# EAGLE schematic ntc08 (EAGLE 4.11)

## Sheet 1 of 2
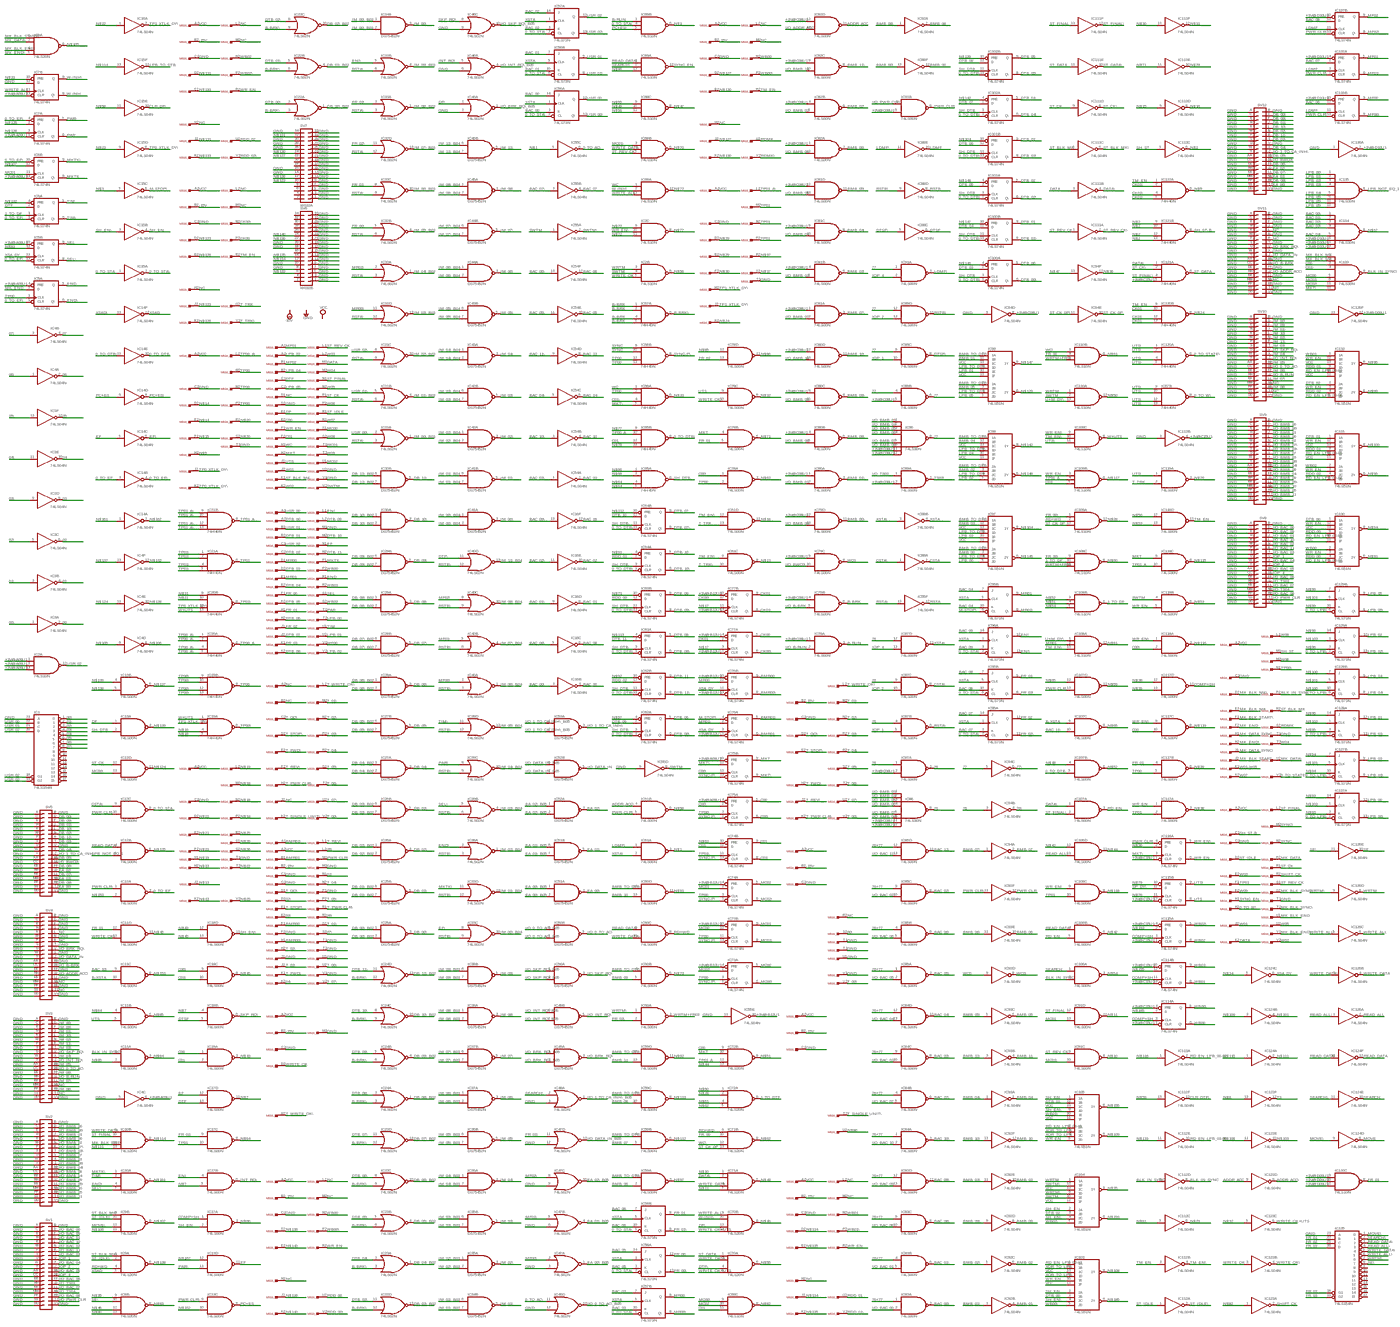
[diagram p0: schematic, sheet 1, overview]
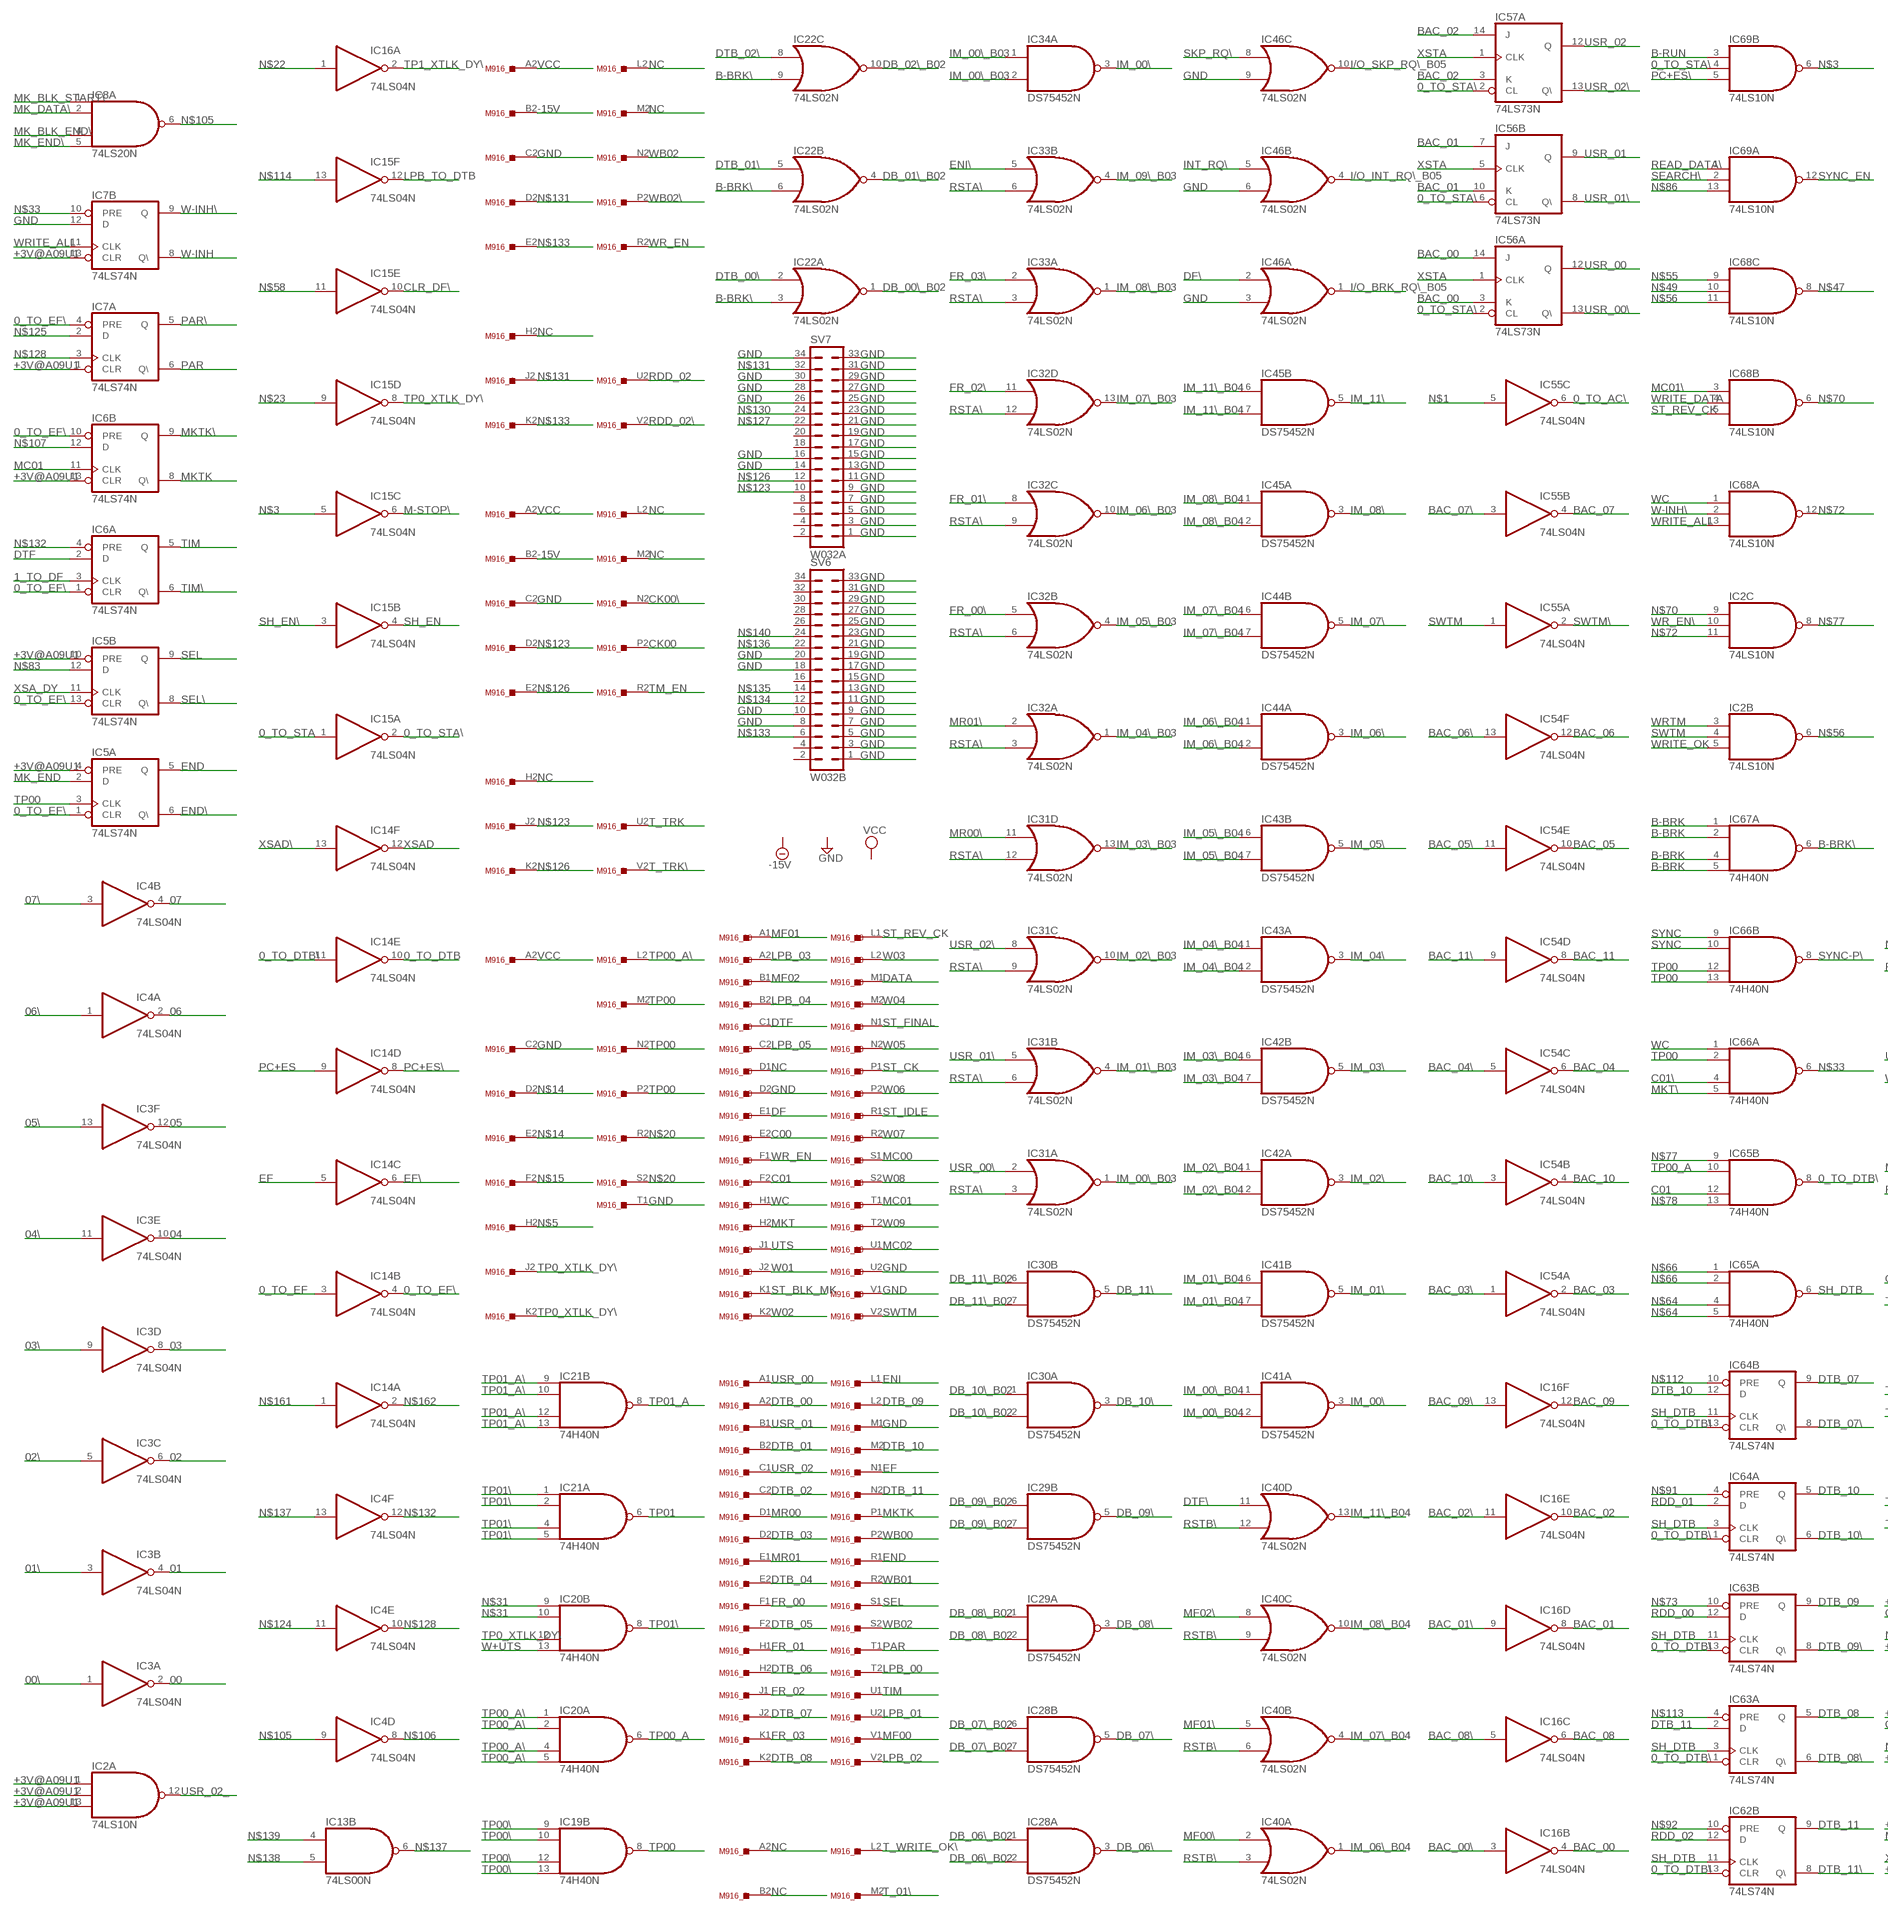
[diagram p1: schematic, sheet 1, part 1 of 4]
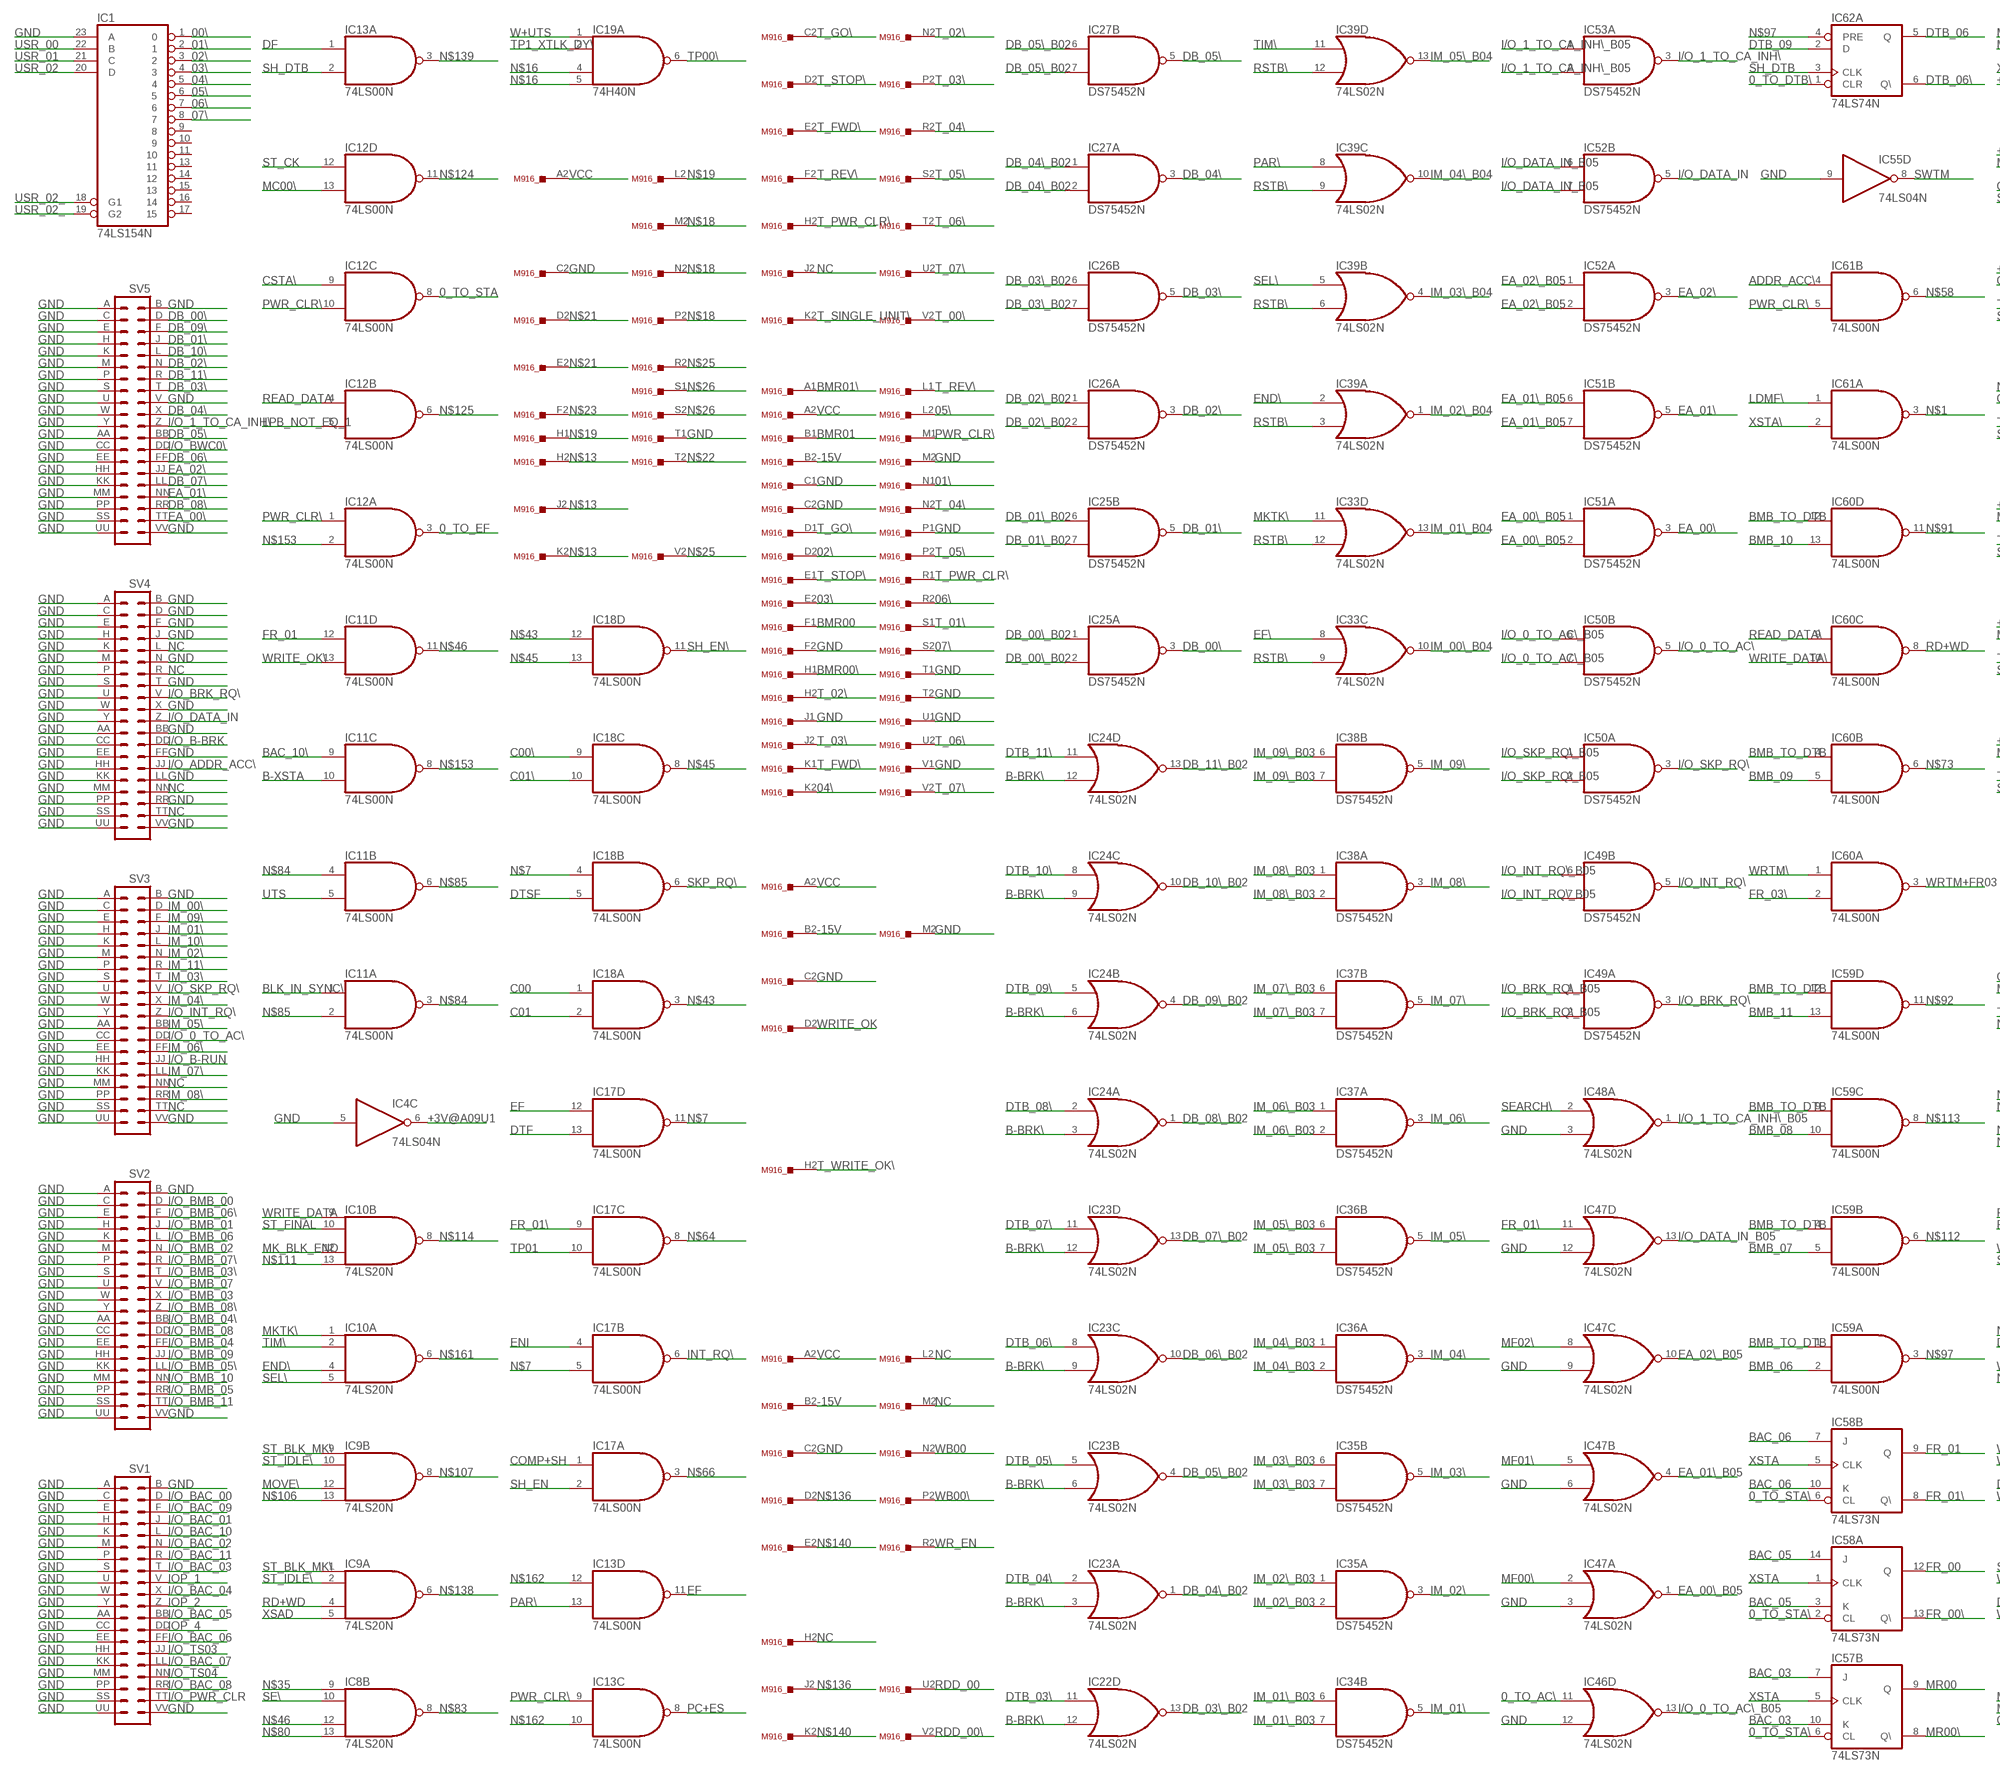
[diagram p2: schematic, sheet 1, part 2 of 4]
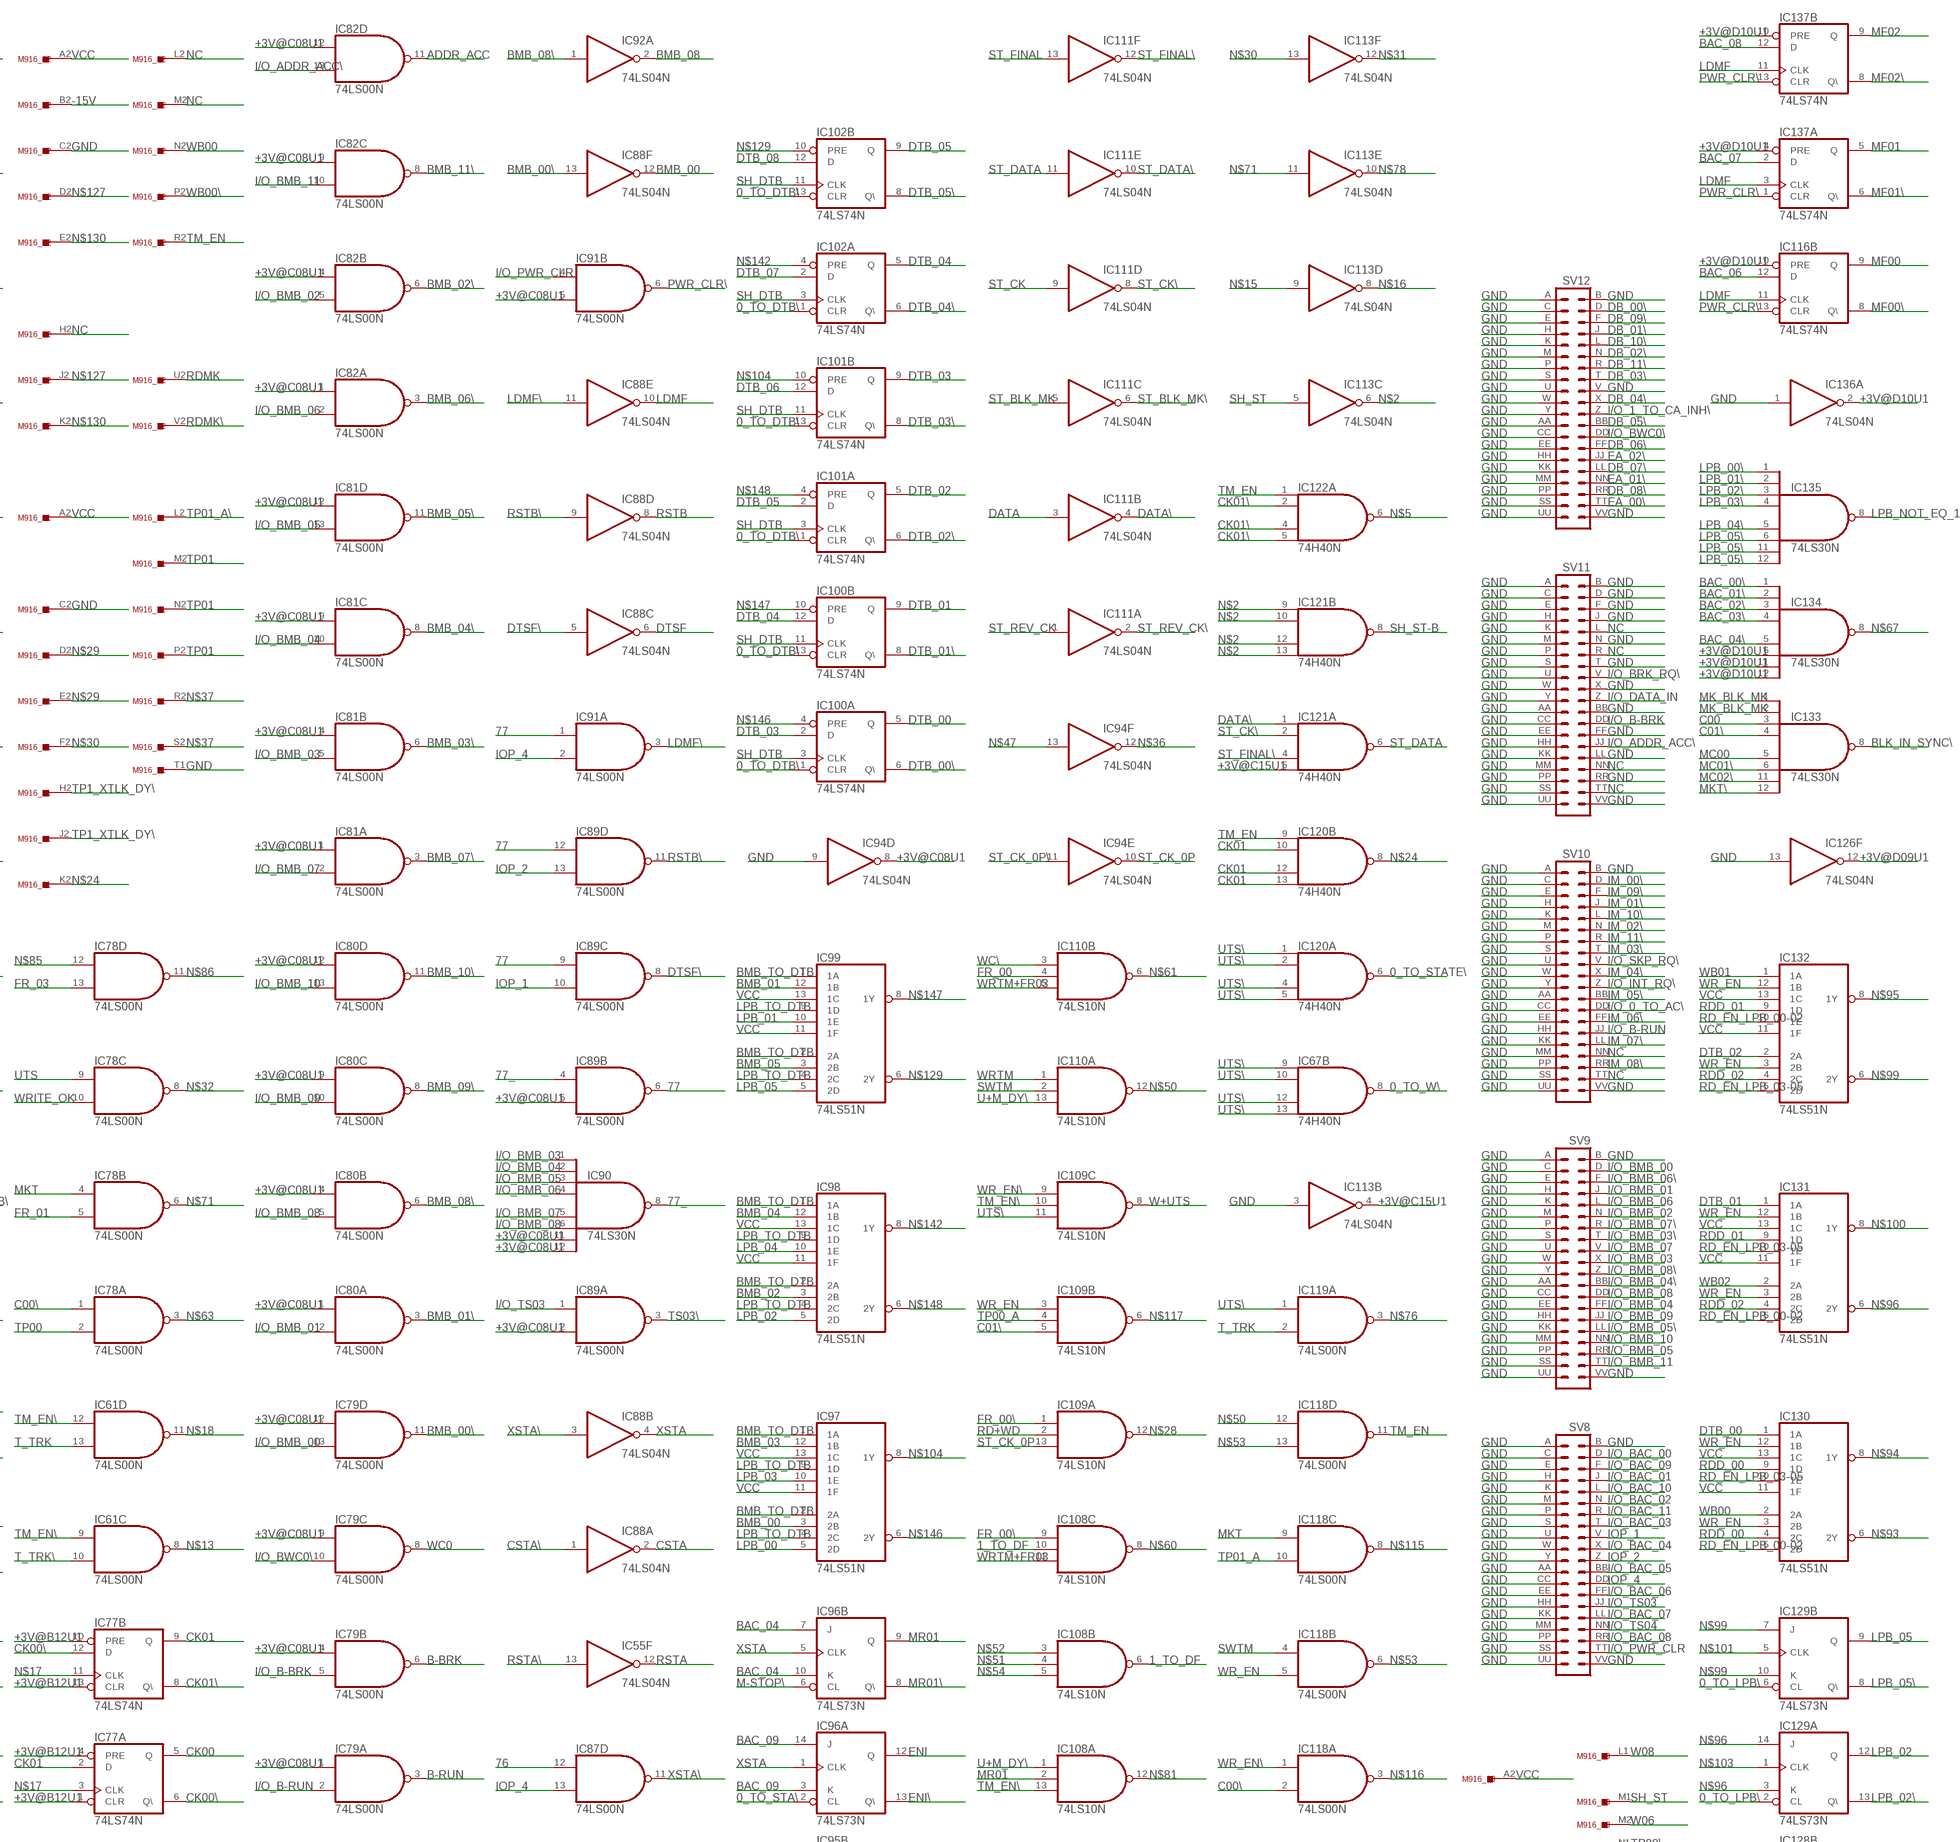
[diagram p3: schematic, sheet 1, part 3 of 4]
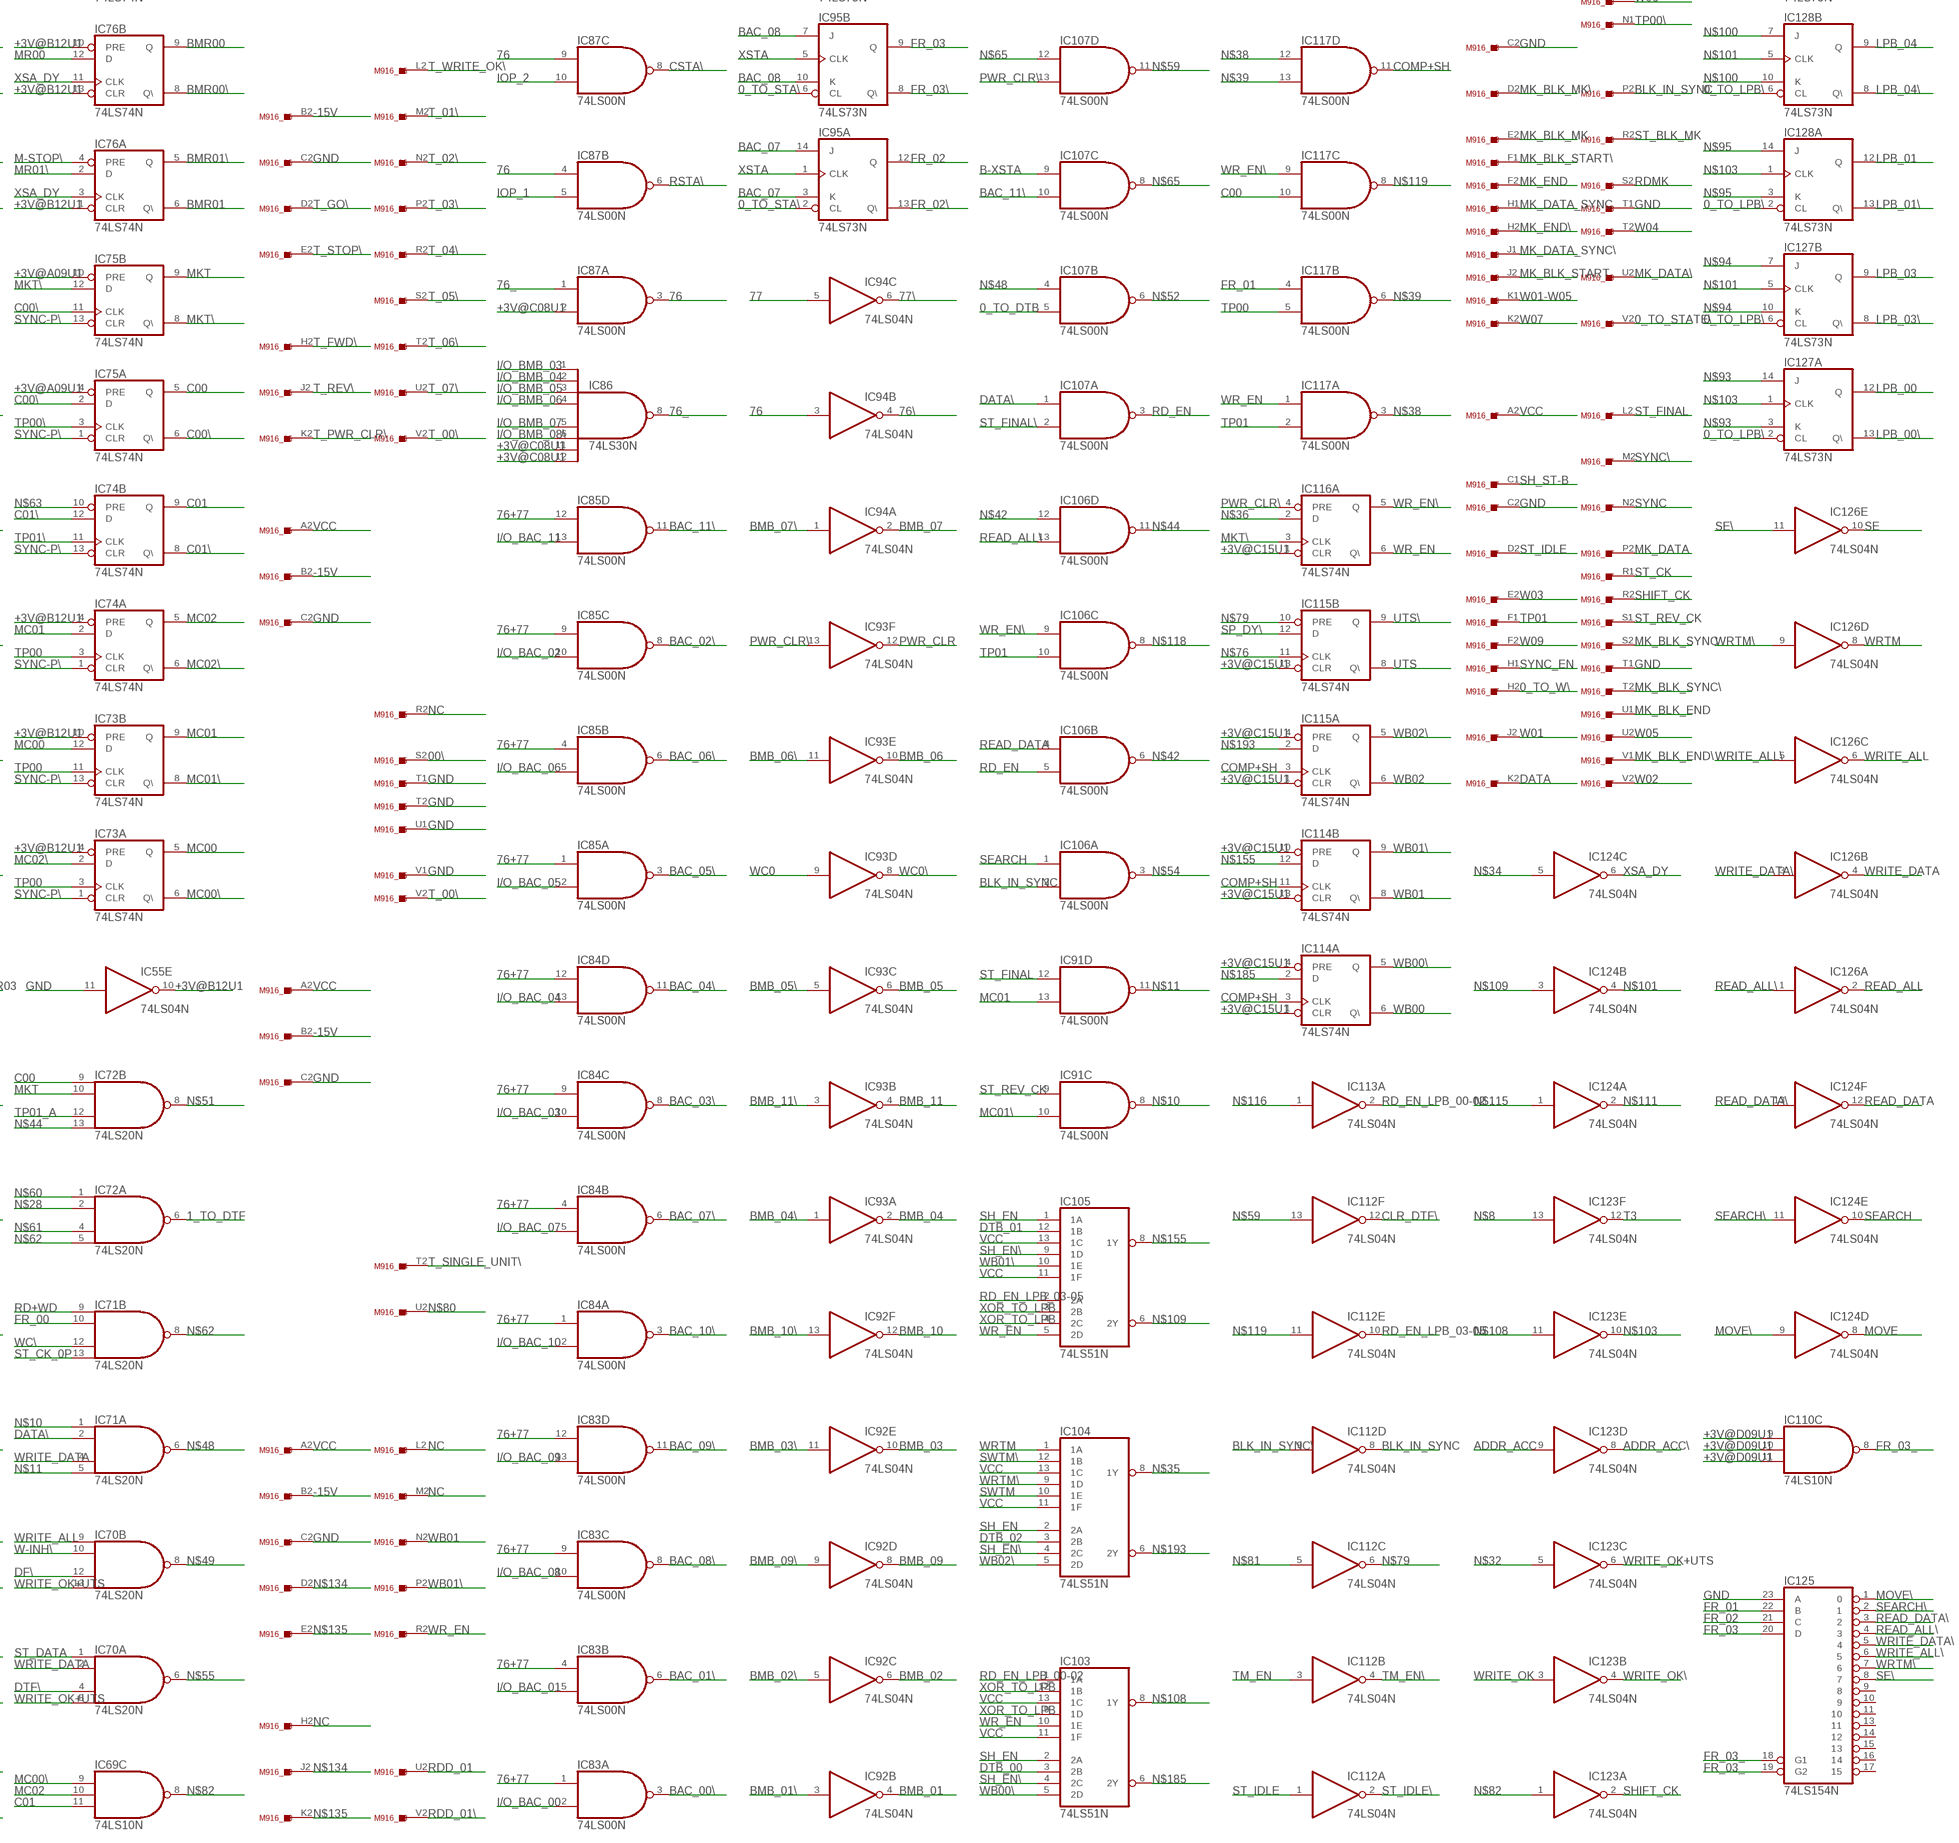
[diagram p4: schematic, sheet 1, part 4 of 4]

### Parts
IC1  74LS154N  [DIL24-6]
IC2  74LS10N  [DIL14]
IC3  74LS04N  [DIL14]
IC4  74LS04N  [DIL14]
IC5  74LS74N  [DIL14]
IC6  74LS74N  [DIL14]
IC7  74LS74N  [DIL14]
IC8  74LS20N  [DIL14]
IC9  74LS20N  [DIL14]
IC10  74LS20N  [DIL14]
IC11  74LS00N  [DIL14]
IC12  74LS00N  [DIL14]
IC13  74LS00N  [DIL14]
IC14  74LS04N  [DIL14]
IC15  74LS04N  [DIL14]
IC16  74LS04N  [DIL14]
IC17  74LS00N  [DIL14]
IC18  74LS00N  [DIL14]
IC19  74H40N  74S20N  [DIL14]
IC20  74H40N  74S20N  [DIL14]
IC21  74H40N  74S20N  [DIL14]
IC22  74LS02N  [DIL14]
IC23  74LS02N  [DIL14]
IC24  74LS02N  [DIL14]
IC25  DS75452N  [DIL08]
IC26  DS75452N  [DIL08]
IC27  DS75452N  [DIL08]
IC28  DS75452N  [DIL08]
IC29  DS75452N  [DIL08]
IC30  DS75452N  [DIL08]
IC31  74LS02N  [DIL14]
IC32  74LS02N  [DIL14]
IC33  74LS02N  [DIL14]
IC34  DS75452N  [DIL08]
IC35  DS75452N  [DIL08]
IC36  DS75452N  [DIL08]
IC37  DS75452N  [DIL08]
IC38  DS75452N  [DIL08]
IC39  74LS02N  [DIL14]
IC40  74LS02N  [DIL14]
IC41  DS75452N  [DIL08]
IC42  DS75452N  [DIL08]
IC43  DS75452N  [DIL08]
IC44  DS75452N  [DIL08]
IC45  DS75452N  [DIL08]
IC46  74LS02N  [DIL14]
IC47  74LS02N  [DIL14]
IC48  74LS02N  [DIL14]
IC49  DS75452N  [DIL08]
IC50  DS75452N  [DIL08]
IC51  DS75452N  [DIL08]
IC52  DS75452N  [DIL08]
IC53  DS75452N  [DIL08]
IC54  74LS04N  [DIL14]
IC55  74LS04N  [DIL14]
IC56  74LS73N  [DIL14]
IC57  74LS73N  [DIL14]
IC58  74LS73N  [DIL14]
IC59  74LS00N  [DIL14]
IC60  74LS00N  [DIL14]
IC61  74LS00N  [DIL14]
IC62  74LS74N  [DIL14]
IC63  74LS74N  [DIL14]
IC64  74LS74N  [DIL14]
IC65  74H40N  74S20N  [DIL14]
IC66  74H40N  74S20N  [DIL14]
IC67  74H40N  74S20N  [DIL14]
IC68  74LS10N  [DIL14]
IC69  74LS10N  [DIL14]
IC70  74LS20N  [DIL14]
IC71  74LS20N  [DIL14]
IC72  74LS20N  [DIL14]
IC73  74LS74N  [DIL14]
IC74  74LS74N  [DIL14]
IC75  74LS74N  [DIL14]
IC76  74LS74N  [DIL14]
IC77  74LS74N  [DIL14]
IC78  74LS00N  [DIL14]
IC79  74LS00N  [DIL14]
IC80  74LS00N  [DIL14]
IC81  74LS00N  [DIL14]
IC82  74LS00N  [DIL14]
IC83  74LS00N  [DIL14]
IC84  74LS00N  [DIL14]
IC85  74LS00N  [DIL14]
IC86  74LS30N  [DIL14]
IC87  74LS00N  [DIL14]
IC88  74LS04N  [DIL14]
IC89  74LS00N  [DIL14]
IC90  74LS30N  [DIL14]
IC91  74LS00N  [DIL14]
IC92  74LS04N  [DIL14]
IC93  74LS04N  [DIL14]
IC94  74LS04N  [DIL14]
IC95  74LS73N  [DIL14]
IC96  74LS73N  [DIL14]
IC97  74LS51N  [DIL14]
IC98  74LS51N  [DIL14]
IC99  74LS51N  [DIL14]
IC100  74LS74N  [DIL14]
IC101  74LS74N  [DIL14]
IC102  74LS74N  [DIL14]
IC103  74LS51N  [DIL14]
IC104  74LS51N  [DIL14]
IC105  74LS51N  [DIL14]
IC106  74LS00N  [DIL14]
IC107  74LS00N  [DIL14]
IC108  74LS10N  [DIL14]
IC109  74LS10N  [DIL14]
IC110  74LS10N  [DIL14]
IC111  74LS04N  [DIL14]
IC112  74LS04N  [DIL14]
IC113  74LS04N  [DIL14]
IC114  74LS74N  [DIL14]
IC115  74LS74N  [DIL14]
IC116  74LS74N  [DIL14]
IC117  74LS00N  [DIL14]
IC118  74LS00N  [DIL14]
IC119  74LS00N  [DIL14]
IC120  74H40N  74S20N  [DIL14]
IC121  74H40N  74S20N  [DIL14]
IC122  74H40N  74S20N  [DIL14]
IC123  74LS04N  [DIL14]
IC124  74LS04N  [DIL14]
IC125  74LS154N  [DIL24-6]
IC126  74LS04N  [DIL14]
IC127  74LS73N  [DIL14]
IC128  74LS73N  [DIL14]
IC129  74LS73N  [DIL14]
IC130  74LS51N  [DIL14]
IC131  74LS51N  [DIL14]
IC132  74LS51N  [DIL14]
IC133  74LS30N  [DIL14]
IC134  74LS30N  [DIL14]
IC135  74LS30N  [DIL14]
IC136  74LS04N  [DIL14]
IC137  74LS74N  [DIL14]
M916_1  M302  M916  [H807]
M916_2  M602  M916  [H807]
M916_3  G888  M916  [H807]
M916_4  M302  M916  [H807]
M916_5  G888  M916  [H807]
M916_6  G888  M916  [H807]
M916_7  M633  M916  [H807]
M916_8  W023  M916  [H807]
M916_9  M916  [H807]
M916_10  M916  [H807]
M916_11  M602  M916  [H807]
M916_12  G888  M916  [H807]
M916_13  G888  M916  [H807]
M916_14  G879  M916  [H807]
M916_15  M633  M916  [H807]
M916_16  W005  M916  [H807]
M916_17  M228B  M916  [H807]
M916_18  M228A  M916  [H807]
SV1  DEC40PIN  [DEC40PIN]
SV2  DEC40PIN  [DEC40PIN]
SV3  DEC40PIN  [DEC40PIN]
SV4  DEC40PIN  [DEC40PIN]
SV5  DEC40PIN  [DEC40PIN]
SV6  W032B  MA17-2  [MA17-2]
SV7  W032A  MA17-2  [MA17-2]
SV8  DEC40PIN  [DEC40PIN]
SV9  DEC40PIN  [DEC40PIN]
SV10  DEC40PIN  [DEC40PIN]
SV11  DEC40PIN  [DEC40PIN]
SV12  DEC40PIN  [DEC40PIN]

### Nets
00: IC3.2(A:O)
00\: IC1.1 IC3.1(A:I) M916_15.S2
0_TO_AC\: IC46.11(D:I0) IC55.6(C:O)
0_TO_DTB: IC14.10(E:O) IC107.5(B:I1)
0_TO_DTB\: IC14.11(E:I) IC62.1(A:CLR) IC62.13(B:CLR) IC63.1(A:CLR) IC63.13(B:CLR) IC64.1(A:CLR) IC64.13(B:CLR) IC65.8(B:O) IC100.1(A:CLR) IC100.13(B:CLR) IC101.1(A:CLR) IC101.13(B:CLR) IC102.1(A:CLR) IC102.13(B:CLR)
0_TO_EF: IC12.3(A:O) IC14.3(B:I)
0_TO_EF\: IC5.1(A:CLR) IC5.13(B:CLR) IC6.1(A:CLR) IC6.10(B:PRE) IC7.4(A:PRE) IC14.4(B:O)
0_TO_LPB\: IC127.2(A:CL) IC127.6(B:CL) IC128.2(A:CL) IC128.6(B:CL) IC129.2(A:CL) IC129.6(B:CL) ; also sheet 2
0_TO_STA: IC12.8(C:O) IC15.1(A:I)
0_TO_STA\: IC15.2(A:O) IC56.2(A:CL) IC56.6(B:CL) IC57.2(A:CL) IC57.6(B:CL) IC58.2(A:CL) IC58.6(B:CL) IC69.4(B:I1) IC95.2(A:CL) IC95.6(B:CL) IC96.2(A:CL)
0_TO_STATE\: IC120.6(A:O) M916_18.V2
0_TO_W\: IC67.8(B:O) M916_17.H2
01: IC3.4(B:O)
01\: IC1.2 IC3.3(B:I) M916_7.N1
1_TO_DF: IC6.3(A:CLK) IC108.6(B:O) IC108.10(C:I1) ; also sheet 2
1_TO_DTF: IC72.6(A:O) ; also sheet 2
02: IC3.6(C:O)
02\: IC1.3 IC3.5(C:I) M916_7.D2
03: IC3.8(D:O)
03\: IC1.4 IC3.9(D:I) M916_7.E2
04: IC3.10(E:O)
04\: IC1.5 IC3.11(E:I) M916_7.K2
05: IC3.12(F:O)
05\: IC1.6 IC3.13(F:I) M916_7.L2
06: IC4.2(A:O)
06\: IC1.7 IC4.1(A:I) M916_7.R2
07: IC4.4(B:O)
07\: IC1.8 IC4.3(B:I) M916_7.S2
76: IC87.3(A:O) IC87.4(B:I0) IC87.9(C:I0) IC87.12(D:I0) IC94.3(B:I)
76+77: IC83.1(A:I0) IC83.4(B:I0) IC83.9(C:I0) IC83.12(D:I0) IC84.1(A:I0) IC84.4(B:I0) IC84.9(C:I0) IC84.12(D:I0) IC85.1(A:I0) IC85.4(B:I0) IC85.9(C:I0) IC85.12(D:I0) ; also sheet 2
76\: IC94.4(B:O) ; also sheet 2
76_: IC86.8(O) IC87.1(A:I0)
77: IC89.6(B:O) IC89.9(C:I0) IC89.12(D:I0) IC91.1(A:I0) IC94.5(C:I)
77\: IC94.6(C:O) ; also sheet 2
77_: IC89.4(B:I0) IC90.8(O)
+3V@A09U1: IC2.1(A:I0) IC2.2(A:I1) IC2.13(A:I2) IC4.6(C:O) IC5.4(A:PRE) IC5.10(B:PRE) IC6.13(B:CLR) IC7.1(A:CLR) IC7.13(B:CLR) IC75.4(A:PRE) IC75.10(B:PRE)
+3V@B12U1: IC55.10(E:O) IC73.4(A:PRE) IC73.10(B:PRE) IC74.4(A:PRE) IC76.1(A:CLR) IC76.10(B:PRE) IC76.13(B:CLR) IC77.1(A:CLR) IC77.4(A:PRE) IC77.10(B:PRE) IC77.13(B:CLR)
+3V@C08U1: IC79.1(A:I0) IC79.4(B:I0) IC79.9(C:I0) IC79.12(D:I0) IC80.1(A:I0) IC80.4(B:I0) IC80.9(C:I0) IC80.12(D:I0) IC81.1(A:I0) IC81.4(B:I0) IC81.9(C:I0) IC81.12(D:I0) IC82.1(A:I0) IC82.4(B:I0) IC82.9(C:I0) IC82.12(D:I0) IC86.11(I6) IC86.12(I7) IC87.2(A:I1) IC89.2(A:I1) IC89.5(B:I1) IC90.11(I6) IC90.12(I7) IC91.5(B:I1) IC94.8(D:O)
+3V@C15U1: IC113.4(B:O) IC114.1(A:CLR) IC114.4(A:PRE) IC114.10(B:PRE) IC114.13(B:CLR) IC115.1(A:CLR) IC115.4(A:PRE) IC115.13(B:CLR) IC116.1(A:CLR) IC121.5(A:I3)
+3V@D09U1: IC110.9(C:I0) IC110.10(C:I1) IC110.11(C:I2) IC126.12(F:O)
+3V@D10U1: IC116.10(B:PRE) IC134.6(I5) IC134.11(I6) IC134.12(I7) IC136.2(A:O) IC137.4(A:PRE) IC137.10(B:PRE) ; also sheet 2
-15V: M916_3.B2 M916_4.B2 M916_5.B2 M916_6.B2 M916_7.B2 M916_12.B2 M916_13.B2 M916_14.B2 M916_15.B2 M916_16.B2
ADDR_ACC: IC82.11(D:O) IC123.9(D:I)
ADDR_ACC\: IC61.4(B:I0) IC123.8(D:O)
B-BRK: IC67.1(A:I0) IC67.2(A:I1) IC67.4(A:I2) IC67.5(A:I3) IC79.6(B:O) ; also sheet 2
B-BRK\: IC22.3(A:I1) IC22.6(B:I1) IC22.9(C:I1) IC22.12(D:I1) IC23.3(A:I1) IC23.6(B:I1) IC23.9(C:I1) IC23.12(D:I1) IC24.3(A:I1) IC24.6(B:I1) IC24.9(C:I1) IC24.12(D:I1) IC67.6(A:O)
B-RUN: IC69.3(B:I0) IC79.3(A:O)
B-XSTA: IC11.10(C:I1) IC107.9(C:I0) ; also sheet 2
BAC_00: IC16.4(B:O) IC56.3(A:K) IC56.14(A:J)
BAC_00\: IC16.3(B:I) IC83.3(A:O) IC134.1(I0)
BAC_01: IC16.8(D:O) IC56.7(B:J) IC56.10(B:K)
BAC_01\: IC16.9(D:I) IC83.6(B:O) IC134.2(I1)
BAC_02: IC16.10(E:O) IC57.3(A:K) IC57.14(A:J)
BAC_02\: IC16.11(E:I) IC85.8(C:O) IC134.3(I2)
BAC_03: IC54.2(A:O) IC57.7(B:J) IC57.10(B:K)
BAC_03\: IC54.1(A:I) IC84.8(C:O) IC134.4(I3)
BAC_04: IC54.6(C:O) IC96.7(B:J) IC96.10(B:K)
BAC_04\: IC54.5(C:I) IC84.11(D:O) IC134.5(I4)
BAC_05: IC54.10(E:O) IC58.3(A:K) IC58.14(A:J)
BAC_05\: IC54.11(E:I) IC85.3(A:O)
BAC_06: IC54.12(F:O) IC58.7(B:J) IC58.10(B:K) IC116.12(B:D)
BAC_06\: IC54.13(F:I) IC85.6(B:O)
BAC_07: IC55.4(B:O) IC95.3(A:K) IC95.14(A:J) IC137.2(A:D)
BAC_07\: IC55.3(B:I) IC84.6(B:O)
BAC_08: IC16.6(C:O) IC95.7(B:J) IC95.10(B:K) IC137.12(B:D)
BAC_08\: IC16.5(C:I) IC83.8(C:O)
BAC_09: IC16.12(F:O) IC96.3(A:K) IC96.14(A:J)
BAC_09\: IC16.13(F:I) IC83.11(D:O)
BAC_10: IC54.4(B:O)
BAC_10\: IC11.9(C:I0) IC54.3(B:I) IC84.3(A:O)
BAC_11: IC54.8(D:O)
BAC_11\: IC54.9(D:I) IC85.11(D:O) IC107.10(C:I1)
BLK_IN_SYNC: IC106.2(A:I1) IC112.8(D:O) M916_18.P2
BLK_IN_SYNC\: IC11.1(A:I0) IC112.9(D:I) IC133.8(O)
BMB_00: IC88.12(F:O) IC97.3(2B)
BMB_00\: IC79.11(D:O) IC88.13(F:I)
BMB_01: IC92.4(B:O) IC99.12(1B)
BMB_01\: IC80.3(A:O) IC92.3(B:I)
BMB_02: IC92.6(C:O) IC98.3(2B)
BMB_02\: IC82.6(B:O) IC92.5(C:I)
BMB_03: IC92.10(E:O) IC97.12(1B)
BMB_03\: IC81.6(B:O) IC92.11(E:I)
BMB_04: IC93.2(A:O) IC98.12(1B)
BMB_04\: IC81.8(C:O) IC93.1(A:I)
BMB_05: IC93.6(C:O) IC99.3(2B)
BMB_05\: IC81.11(D:O) IC93.5(C:I)
BMB_06: IC59.2(A:I1) IC93.10(E:O)
BMB_06\: IC82.3(A:O) IC93.11(E:I)
BMB_07: IC59.5(B:I1) IC94.2(A:O)
BMB_07\: IC81.3(A:O) IC94.1(A:I)
BMB_08: IC59.10(C:I1) IC92.2(A:O)
BMB_08\: IC80.6(B:O) IC92.1(A:I)
BMB_09: IC60.5(B:I1) IC92.8(D:O)
BMB_09\: IC80.8(C:O) IC92.9(D:I)
BMB_10: IC60.13(D:I1) IC92.12(F:O)
BMB_10\: IC80.11(D:O) IC92.13(F:I)
BMB_11: IC59.13(D:I1) IC93.4(B:O)
BMB_11\: IC82.8(C:O) IC93.3(B:I)
BMB_TO_DTB: IC59.1(A:I0) IC59.4(B:I0) IC59.9(C:I0) IC59.12(D:I0) IC60.4(B:I0) IC60.12(D:I0) IC97.1(1A) IC97.2(2A) IC98.1(1A) IC98.2(2A) IC99.1(1A) IC99.2(2A) ; also sheet 2
BMR00: IC76.9(B:Q) M916_7.F1
BMR00\: IC76.8(B:Q\) M916_7.H1
BMR01: IC76.6(A:Q\) M916_7.B1
BMR01\: IC76.5(A:Q) M916_7.A1
C00: IC18.1(A:I0) IC72.9(B:I0) IC75.5(A:Q) IC117.10(C:I1) IC133.3(I2) M916_10.E2
C00\: IC18.9(C:I0) IC75.2(A:D) IC75.6(A:Q\) IC75.11(B:CLK) IC78.1(A:I0) IC118.2(A:I1)
C01: IC18.2(A:I1) IC65.12(B:I2) IC69.11(C:I2) IC74.9(B:Q) M916_10.F2
C01\: IC18.10(C:I1) IC66.4(A:I2) IC74.8(B:Q\) IC74.12(B:D) IC109.5(B:I2) IC133.4(I3)
CK00: IC77.5(A:Q) M916_3.P2
CK00\: IC77.6(A:Q\) IC77.12(B:D) M916_3.N2
CK01: IC77.2(A:D) IC77.9(B:Q) IC120.10(B:I1) IC120.12(B:I2) IC120.13(B:I3)
CK01\: IC77.8(B:Q\) IC122.2(A:I1) IC122.4(A:I2) IC122.5(A:I3)
CLR_DF\: IC15.10(E:O) ; also sheet 2
CLR_DTF\: IC112.12(F:O) ; also sheet 2
COMP+SH: IC17.1(A:I0) IC114.3(A:CLK) IC114.11(B:CLK) IC115.3(A:CLK) IC117.11(D:O)
CSTA: IC88.2(A:O) ; also sheet 2
CSTA\: IC12.9(C:I0) IC87.8(C:O) IC88.1(A:I)
DATA: IC111.3(B:I) M916_10.M1 M916_17.K2
DATA\: IC71.2(A:I1) IC107.1(A:I0) IC111.4(B:O) IC121.1(A:I0)
DB_00\: IC25.3(A:O) SV5.D SV12.D
DB_00\_B02: IC22.1(A:O) IC25.1(A:I0) IC25.2(A:I1)
DB_01\: IC25.5(B:O) SV5.J SV12.J
DB_01\_B02: IC22.4(B:O) IC25.6(B:I0) IC25.7(B:I1)
DB_02\: IC26.3(A:O) SV5.N SV12.N
DB_02\_B02: IC22.10(C:O) IC26.1(A:I0) IC26.2(A:I1)
DB_03\: IC26.5(B:O) SV5.T SV12.T
DB_03\_B02: IC22.13(D:O) IC26.6(B:I0) IC26.7(B:I1)
DB_04\: IC27.3(A:O) SV5.X SV12.X
DB_04\_B02: IC23.1(A:O) IC27.1(A:I0) IC27.2(A:I1)
DB_05\: IC27.5(B:O) SV5.BB SV12.BB
DB_05\_B02: IC23.4(B:O) IC27.6(B:I0) IC27.7(B:I1)
DB_06\: IC28.3(A:O) SV5.FF SV12.FF
DB_06\_B02: IC23.10(C:O) IC28.1(A:I0) IC28.2(A:I1)
DB_07\: IC28.5(B:O) SV5.LL SV12.LL
DB_07\_B02: IC23.13(D:O) IC28.6(B:I0) IC28.7(B:I1)
DB_08\: IC29.3(A:O) SV5.RR SV12.RR
DB_08\_B02: IC24.1(A:O) IC29.1(A:I0) IC29.2(A:I1)
DB_09\: IC29.5(B:O) SV5.F SV12.F
DB_09\_B02: IC24.4(B:O) IC29.6(B:I0) IC29.7(B:I1)
DB_10\: IC30.3(A:O) SV5.L SV12.L
DB_10\_B02: IC24.10(C:O) IC30.1(A:I0) IC30.2(A:I1)
DB_11\: IC30.5(B:O) SV5.R SV12.R
DB_11\_B02: IC24.13(D:O) IC30.6(B:I0) IC30.7(B:I1)
DF: IC13.1(A:I0) M916_10.E1 ; also sheet 2
DF\: IC46.2(A:I0) IC70.12(B:I2) ; also sheet 2
DTB_00: IC100.5(A:Q) IC103.3(2B) IC130.1(1A) M916_9.A2
DTB_00\: IC22.2(A:I0) IC100.6(A:Q\)
DTB_01: IC100.9(B:Q) IC105.12(1B) IC131.1(1A) M916_9.B2
DTB_01\: IC22.5(B:I0) IC100.8(B:Q\)
DTB_02: IC101.5(A:Q) IC104.3(2B) IC132.2(2A) M916_9.C2
DTB_02\: IC22.8(C:I0) IC101.6(A:Q\)
DTB_03: IC100.2(A:D) IC101.9(B:Q) M916_9.D2
DTB_03\: IC22.11(D:I0) IC101.8(B:Q\)
DTB_04: IC100.12(B:D) IC102.5(A:Q) M916_9.E2
DTB_04\: IC23.2(A:I0) IC102.6(A:Q\)
DTB_05: IC101.2(A:D) IC102.9(B:Q) M916_9.F2
DTB_05\: IC23.5(B:I0) IC102.8(B:Q\)
DTB_06: IC62.5(A:Q) IC101.12(B:D) M916_9.H2
DTB_06\: IC23.8(C:I0) IC62.6(A:Q\)
DTB_07: IC64.9(B:Q) IC102.2(A:D) M916_9.J2
DTB_07\: IC23.11(D:I0) IC64.8(B:Q\)
DTB_08: IC63.5(A:Q) IC102.12(B:D) M916_9.K2
DTB_08\: IC24.2(A:I0) IC63.6(A:Q\)
DTB_09: IC62.2(A:D) IC63.9(B:Q) M916_9.L2
DTB_09\: IC24.5(B:I0) IC63.8(B:Q\)
DTB_10: IC64.5(A:Q) IC64.12(B:D) M916_9.M2
DTB_10\: IC24.8(C:I0) IC64.6(A:Q\)
DTB_11: IC62.9(B:Q) IC63.2(A:D) M916_9.N2
DTB_11\: IC24.11(D:I0) IC62.8(B:Q\)
DTF: IC6.2(A:D) IC17.13(D:I1) M916_10.C1 ; also sheet 2
DTF\: IC40.11(D:I0) IC70.4(A:I2) ; also sheet 2
DTSF: IC18.5(B:I1) IC88.6(C:O)
DTSF\: IC88.5(C:I) IC89.8(C:O)
EA_00\: IC51.3(A:O) SV5.TT SV12.TT
EA_00\_B05: IC47.1(A:O) IC51.1(A:I0) IC51.2(A:I1)
EA_01\: IC51.5(B:O) SV5.NN SV12.NN
EA_01\_B05: IC47.4(B:O) IC51.6(B:I0) IC51.7(B:I1)
EA_02\: IC52.3(A:O) SV5.JJ SV12.JJ
EA_02\_B05: IC47.10(C:O) IC52.1(A:I0) IC52.2(A:I1)
EF: IC13.11(D:O) IC14.5(C:I) IC17.12(D:I0) M916_9.N1
EF\: IC14.6(C:O) IC33.8(C:I0)
END: IC5.5(A:Q) M916_9.R1
END\: IC5.6(A:Q\) IC10.4(A:I2) IC39.2(A:I0)
ENI: IC17.4(B:I0) IC96.12(A:Q) M916_9.L1
ENI\: IC33.5(B:I0) IC96.13(A:Q\)
FR_00: IC58.12(A:Q) IC71.10(B:I1) IC110.4(B:I1) M916_9.F1
FR_00\: IC32.5(B:I0) IC58.13(A:Q\) IC108.9(C:I0) IC109.1(A:I0)
FR_01: IC11.12(D:I0) IC58.9(B:Q) IC78.5(B:I1) IC117.4(B:I0) IC125.22(B) M916_9.H1 ; also sheet 2
FR_01\: IC17.9(C:I0) IC32.8(C:I0) IC47.11(D:I0) IC58.8(B:Q\)
FR_02: IC95.12(A:Q) IC125.21(C) M916_9.J1
FR_02\: IC32.11(D:I0) IC95.13(A:Q\)
FR_03: IC78.13(D:I1) IC95.9(B:Q) IC125.20(D) M916_9.K1
FR_03\: IC33.2(A:I0) IC60.2(A:I1) IC95.8(B:Q\)
FR_03_: IC110.8(C:O) IC125.18(G1) IC125.19(G2)
GND: IC1.23(A) IC4.5(C:I) IC7.12(B:D) IC46.3(A:I1) IC46.6(B:I1) IC46.9(C:I1) IC46.12(D:I1) IC47.3(A:I1) IC47.6(B:I1) IC47.9(C:I1) IC47.12(D:I1) IC48.3(A:I1) IC55.9(D:I) IC55.11(E:I) IC94.9(D:I) IC113.3(B:I) IC125.23(A) IC126.13(F:I) IC136.1(A:I) M916_1.C2 M916_1.T1 M916_2.C2 M916_2.T1 M916_3.C2 M916_4.C2 M916_5.C2 M916_6.C2 M916_6.M2 M916_7.C1 M916_7.C2 M916_7.F2 M916_7.J1 M916_7.M2 M916_7.P1 M916_7.T1 M916_7.T2 M916_7.U1 M916_7.V1 M916_9.M1 M916_10.D2 M916_10.U2 M916_10.V1 M916_11.C2 M916_11.T1 M916_12.C2 M916_13.C2 M916_14.C2 M916_15.C2 M916_15.T1 M916_15.T2 M916_15.U1 M916_15.V1 M916_16.C2 M916_17.C2 M916_17.T1 M916_18.C2 M916_18.T1 SV1.A SV1.AA SV1.B SV1.C SV1.CC SV1.E SV1.EE SV1.H SV1.HH SV1.K SV1.KK SV1.M SV1.MM SV1.P SV1.PP SV1.S SV1.SS SV1.U SV1.UU SV1.VV SV1.W SV1.Y SV2.A SV2.AA SV2.B SV2.C SV2.CC SV2.E SV2.EE SV2.H SV2.HH SV2.K SV2.KK SV2.M SV2.MM SV2.P SV2.PP SV2.S SV2.SS SV2.U SV2.UU SV2.VV SV2.W SV2.Y SV3.A SV3.AA SV3.B SV3.C SV3.CC SV3.E SV3.EE SV3.H SV3.HH SV3.K SV3.KK SV3.M SV3.MM SV3.P SV3.PP SV3.S SV3.SS SV3.U SV3.UU SV3.VV SV3.W SV3.Y SV4.A SV4.AA SV4.B SV4.BB SV4.C SV4.CC SV4.D SV4.E SV4.EE SV4.F SV4.FF SV4.H SV4.HH SV4.J SV4.K SV4.KK SV4.LL SV4.M SV4.MM SV4.N SV4.P SV4.PP SV4.RR SV4.S SV4.SS SV4.T SV4.U SV4.UU SV4.VV SV4.W SV4.X SV4.Y SV5.A SV5.AA SV5.B SV5.C SV5.CC SV5.E SV5.EE SV5.H SV5.HH SV5.K SV5.KK SV5.M SV5.MM SV5.P SV5.PP SV5.S SV5.SS SV5.U SV5.UU SV5.V SV5.VV SV5.W SV5.Y SV6.1 SV6.3 SV6.5 SV6.7 SV6.8 SV6.9 SV6.10 SV6.11 SV6.13 SV6.15 SV6.17 SV6.18 SV6.19 SV6.20 SV6.21 SV6.23 SV6.25 SV6.27 SV6.29 SV6.31 SV6.33 SV7.1 SV7.3 SV7.5 SV7.7 SV7.9 SV7.11 SV7.13 SV7.14 SV7.15 SV7.16 SV7.17 SV7.19 SV7.21 SV7.23 SV7.25 SV7.26 SV7.27 SV7.28 SV7.29 SV7.30 SV7.31 SV7.33 SV7.34 SV8.A SV8.AA SV8.B SV8.C SV8.CC SV8.E SV8.EE SV8.H SV8.HH SV8.K SV8.KK SV8.M SV8.MM SV8.P SV8.PP SV8.S SV8.SS SV8.U SV8.UU SV8.VV SV8.W SV8.Y SV9.A SV9.AA SV9.B SV9.C SV9.CC SV9.E SV9.EE SV9.H SV9.HH SV9.K SV9.KK SV9.M SV9.MM SV9.P SV9.PP SV9.S SV9.SS SV9.U SV9.UU SV9.VV SV9.W SV9.Y SV10.A SV10.AA SV10.B SV10.C SV10.CC SV10.E SV10.EE SV10.H SV10.HH SV10.K SV10.KK SV10.M SV10.MM SV10.P SV10.PP SV10.S SV10.SS SV10.U SV10.UU SV10.VV SV10.W SV10.Y SV11.A SV11.AA SV11.B SV11.BB SV11.C SV11.CC SV11.D SV11.E SV11.EE SV11.F SV11.FF SV11.H SV11.HH SV11.J SV11.K SV11.KK SV11.LL SV11.M SV11.MM SV11.N SV11.P SV11.PP SV11.RR SV11.S SV11.SS SV11.T SV11.U SV11.UU SV11.VV SV11.W SV11.X SV11.Y SV12.A SV12.AA SV12.B SV12.C SV12.CC SV12.E SV12.EE SV12.H SV12.HH SV12.K SV12.KK SV12.M SV12.MM SV12.P SV12.PP SV12.S SV12.SS SV12.U SV12.UU SV12.V SV12.VV SV12.W SV12.Y ; also sheet 2
I/O_0_TO_AC\: IC50.5(B:O) SV3.DD SV10.DD
I/O_0_TO_AC\_B05: IC46.13(D:O) IC50.6(B:I0) IC50.7(B:I1)
I/O_1_TO_CA_INH\: IC53.3(A:O) SV5.Z SV12.Z
I/O_1_TO_CA_INH\_B05: IC48.1(A:O) IC53.1(A:I0) IC53.2(A:I1)
I/O_ADDR_ACC\: IC82.13(D:I1) SV4.JJ SV11.JJ
I/O_B-BRK: IC79.5(B:I1) SV4.DD SV11.DD
I/O_B-RUN: IC79.2(A:I1) SV3.JJ SV10.JJ
I/O_BAC_00: IC83.2(A:I1) SV1.D SV8.D
I/O_BAC_01: IC83.5(B:I1) SV1.J SV8.J
I/O_BAC_02: IC85.10(C:I1) SV1.N SV8.N
I/O_BAC_03: IC84.10(C:I1) SV1.T SV8.T
I/O_BAC_04: IC84.13(D:I1) SV1.X SV8.X
I/O_BAC_05: IC85.2(A:I1) SV1.BB SV8.BB
I/O_BAC_06: IC85.5(B:I1) SV1.FF SV8.FF
I/O_BAC_07: IC84.5(B:I1) SV1.LL SV8.LL
I/O_BAC_08: IC83.10(C:I1) SV1.RR SV8.RR
I/O_BAC_09: IC83.13(D:I1) SV1.F SV8.F
I/O_BAC_10: IC84.2(A:I1) SV1.L SV8.L
I/O_BAC_11: IC85.13(D:I1) SV1.R SV8.R
I/O_BMB_00: IC79.13(D:I1) SV2.D SV9.D
I/O_BMB_01: IC80.2(A:I1) SV2.J SV9.J
I/O_BMB_02: IC82.5(B:I1) SV2.N SV9.N
I/O_BMB_03: IC81.5(B:I1) IC86.1(I0) IC90.1(I0) SV2.X SV9.X
I/O_BMB_03\: SV2.T SV9.T
I/O_BMB_04: IC81.10(C:I1) IC86.2(I1) IC90.2(I1) SV2.FF SV9.FF
I/O_BMB_04\: SV2.BB SV9.BB
I/O_BMB_05: IC81.13(D:I1) IC86.3(I2) IC90.3(I2) SV2.RR SV9.RR
I/O_BMB_05\: SV2.LL SV9.LL
I/O_BMB_06: IC82.2(A:I1) IC86.4(I3) IC90.4(I3) SV2.L SV9.L
I/O_BMB_06\: SV2.F SV9.F
I/O_BMB_07: IC81.2(A:I1) IC86.5(I4) IC90.5(I4) SV2.V SV9.V
I/O_BMB_07\: SV2.R SV9.R
I/O_BMB_08: IC80.5(B:I1) IC90.6(I5) SV2.DD SV9.DD
I/O_BMB_08\: IC86.6(I5) SV2.Z SV9.Z
I/O_BMB_09: IC80.10(C:I1) SV2.JJ SV9.JJ
I/O_BMB_10: IC80.13(D:I1) SV2.NN SV9.NN
I/O_BMB_11: IC82.10(C:I1) SV2.TT SV9.TT
I/O_BRK_RQ\: IC49.3(A:O) SV4.V SV11.V
I/O_BRK_RQ\_B05: IC46.1(A:O) IC49.1(A:I0) IC49.2(A:I1)
I/O_BWC0\: IC79.10(C:I1) SV5.DD SV12.DD
I/O_DATA_IN: IC52.5(B:O) SV4.Z SV11.Z
I/O_DATA_IN_B05: IC47.13(D:O) IC52.6(B:I0) IC52.7(B:I1)
I/O_INT_RQ\: IC49.5(B:O) SV3.Z SV10.Z
I/O_INT_RQ\_B05: IC46.4(B:O) IC49.6(B:I0) IC49.7(B:I1)
I/O_PWR_CLR: IC91.4(B:I0) SV1.TT SV8.TT
I/O_SKP_RQ\: IC50.3(A:O) SV3.V SV10.V
I/O_SKP_RQ\_B05: IC46.10(C:O) IC50.1(A:I0) IC50.2(A:I1)
I/O_TS03: IC89.1(A:I0) SV1.JJ SV8.JJ
I/O_TS04: SV1.NN SV8.NN
IM_00\: IC34.3(A:O) IC41.3(A:O) SV3.D SV10.D
IM_00\_B03: IC31.1(A:O) IC34.1(A:I0) IC34.2(A:I1)
IM_00\_B04: IC33.10(C:O) IC41.1(A:I0) IC41.2(A:I1)
IM_01\: IC34.5(B:O) IC41.5(B:O) SV3.J SV10.J
IM_01\_B03: IC31.4(B:O) IC34.6(B:I0) IC34.7(B:I1)
IM_01\_B04: IC33.13(D:O) IC41.6(B:I0) IC41.7(B:I1)
IM_02\: IC35.3(A:O) IC42.3(A:O) SV3.N SV10.N
IM_02\_B03: IC31.10(C:O) IC35.1(A:I0) IC35.2(A:I1)
IM_02\_B04: IC39.1(A:O) IC42.1(A:I0) IC42.2(A:I1)
IM_03\: IC35.5(B:O) IC42.5(B:O) SV3.T SV10.T
IM_03\_B03: IC31.13(D:O) IC35.6(B:I0) IC35.7(B:I1)
IM_03\_B04: IC39.4(B:O) IC42.6(B:I0) IC42.7(B:I1)
IM_04\: IC36.3(A:O) IC43.3(A:O) SV3.X SV10.X
IM_04\_B03: IC32.1(A:O) IC36.1(A:I0) IC36.2(A:I1)
IM_04\_B04: IC39.10(C:O) IC43.1(A:I0) IC43.2(A:I1)
IM_05\: IC36.5(B:O) IC43.5(B:O) SV3.BB SV10.BB
IM_05\_B03: IC32.4(B:O) IC36.6(B:I0) IC36.7(B:I1)
IM_05\_B04: IC39.13(D:O) IC43.6(B:I0) IC43.7(B:I1)
IM_06\: IC37.3(A:O) IC44.3(A:O) SV3.FF SV10.FF
IM_06\_B03: IC32.10(C:O) IC37.1(A:I0) IC37.2(A:I1)
IM_06\_B04: IC40.1(A:O) IC44.1(A:I0) IC44.2(A:I1)
IM_07\: IC37.5(B:O) IC44.5(B:O) SV3.LL SV10.LL
IM_07\_B03: IC32.13(D:O) IC37.6(B:I0) IC37.7(B:I1)
IM_07\_B04: IC40.4(B:O) IC44.6(B:I0) IC44.7(B:I1)
IM_08\: IC38.3(A:O) IC45.3(A:O) SV3.RR SV10.RR
IM_08\_B03: IC33.1(A:O) IC38.1(A:I0) IC38.2(A:I1)
IM_08\_B04: IC40.10(C:O) IC45.1(A:I0) IC45.2(A:I1)
IM_09\: IC38.5(B:O) SV3.F SV10.F
IM_09\_B03: IC33.4(B:O) IC38.6(B:I0) IC38.7(B:I1)
IM_10\: SV3.L SV10.L
IM_11\: IC45.5(B:O) SV3.R SV10.R
IM_11\_B04: IC40.13(D:O) IC45.6(B:I0) IC45.7(B:I1)
INT_RQ\: IC17.6(B:O) IC46.5(B:I0)
IOP_1: IC87.5(B:I1) IC89.10(C:I1) SV1.V SV8.V
IOP_2: IC87.10(C:I1) IC89.13(D:I1) SV1.Z SV8.Z
IOP_4: IC87.13(D:I1) IC91.2(A:I1) SV1.DD SV8.DD
LDMF: IC88.10(E:O) IC116.11(B:CLK) IC137.3(A:CLK) IC137.11(B:CLK)
LDMF\: IC61.1(A:I0) IC88.11(E:I) IC91.3(A:O)
LPB_00: IC97.5(2D) IC127.12(A:Q) M916_9.T2
LPB_00\: IC127.13(A:Q\) IC135.1(I0)
LPB_01: IC99.10(1E) IC128.12(A:Q) M916_9.U2
LPB_01\: IC128.13(A:Q\) IC135.2(I1)
LPB_02: IC98.5(2D) IC129.12(A:Q) M916_9.V2
LPB_02\: IC129.13(A:Q\) IC135.3(I2)
LPB_03: IC97.10(1E) IC127.9(B:Q) M916_10.A2
LPB_03\: IC127.8(B:Q\) IC135.4(I3)
LPB_04: IC98.10(1E) IC128.9(B:Q) M916_10.B2
LPB_04\: IC128.8(B:Q\) IC135.5(I4)
LPB_05: IC99.5(2D) IC129.9(B:Q) M916_10.C2
LPB_05\: IC129.8(B:Q\) IC135.6(I5) IC135.11(I6) IC135.12(I7)
LPB_NOT_EQ_1: IC12.5(B:I1) IC135.8(O)
LPB_TO_DTB: IC15.12(F:O) IC97.4(2C) IC97.9(1D) IC98.4(2C) IC98.9(1D) IC99.4(2C) IC99.9(1D)
M-STOP\: IC15.6(C:O) IC76.4(A:PRE) IC96.6(B:CL) ; also sheet 2
MC00: IC73.5(A:Q) IC73.12(B:D) IC133.5(I4) M916_10.S1
MC00\: IC12.13(D:I1) IC69.9(C:I0) IC73.6(A:Q\)
MC01: IC6.11(B:CLK) IC73.9(B:Q) IC74.2(A:D) IC91.13(D:I1) M916_10.T1
MC01\: IC68.3(B:I0) IC73.8(B:Q\) IC91.10(C:I1) IC133.6(I5)
MC02: IC69.10(C:I1) IC74.5(A:Q) M916_10.U1 ; also sheet 2
MC02\: IC73.2(A:D) IC74.6(A:Q\) IC133.11(I6)
MF00: IC116.9(B:Q) M916_9.V1
MF00\: IC40.2(A:I0) IC47.2(A:I0) IC116.8(B:Q\)
MF01: IC137.5(A:Q) M916_10.A1
MF01\: IC40.5(B:I0) IC47.5(B:I0) IC137.6(A:Q\)
MF02: IC137.9(B:Q) M916_10.B1
MF02\: IC40.8(C:I0) IC47.8(C:I0) IC137.8(B:Q\)
MK_BLK_END: IC10.12(B:I2) M916_17.U1
MK_BLK_END\: IC8.4(A:I2) M916_17.V1
MK_BLK_MK: IC133.1(I0) IC133.2(I1) M916_18.E2
MK_BLK_MK\: M916_18.D2
MK_BLK_START: M916_18.J2
MK_BLK_START\: IC8.1(A:I0) M916_18.F1
MK_BLK_SYNC: M916_17.S2
MK_BLK_SYNC\: M916_17.T2
MK_DATA: M916_17.P2
MK_DATA\: IC8.2(A:I1) M916_18.U2
MK_DATA_SYNC: M916_18.H1
MK_DATA_SYNC\: M916_18.J1
MK_END: IC5.2(A:D) M916_18.F2
MK_END\: IC8.5(A:I3) M916_18.H2
MKT: IC72.10(B:I1) IC75.9(B:Q) IC78.4(B:I0) IC118.9(C:I0) M916_10.H2
MKT\: IC66.5(A:I3) IC75.8(B:Q\) IC75.12(B:D) IC116.3(A:CLK) IC133.12(I7)
MKTK: IC6.8(B:Q\) M916_9.P1
MKTK\: IC6.9(B:Q) IC10.1(A:I0) IC33.11(D:I0)
MOVE: IC124.8(D:O)
MOVE\: IC9.12(B:I2) IC124.9(D:I) IC125.1
MR00: IC57.9(B:Q) IC76.12(B:D) M916_9.D1
MR00\: IC31.11(D:I0) IC57.8(B:Q\)
MR01: IC96.9(B:Q) IC108.2(A:I1) M916_9.E1
MR01\: IC32.2(A:I0) IC76.2(A:D) IC96.8(B:Q\)
N$1: IC55.5(C:I) IC61.3(A:O)
N$2: IC113.6(C:O) IC121.9(B:I0) IC121.10(B:I1) IC121.12(B:I2) IC121.13(B:I3)
N$3: IC15.5(C:I) IC69.6(B:O)
N$5: IC122.6(A:O) M916_2.H2
N$7: IC17.5(B:I1) IC17.11(D:O) IC18.4(B:I0)
N$8: IC123.13(F:I) ; also sheet 2
N$10: IC71.1(A:I0) IC91.8(C:O)
N$11: IC71.5(A:I3) IC91.11(D:O)
N$13: IC61.8(C:O) M916_1.H2 M916_1.J2 M916_1.K2
N$14: M916_2.D2 M916_2.E2
N$15: IC113.9(D:I) M916_2.F2
N$16: IC19.4(A:I2) IC19.5(A:I3) IC113.8(D:O)
N$17: IC77.3(A:CLK) IC77.11(B:CLK) ; also sheet 2
N$18: IC61.11(D:O) M916_1.M2 M916_1.N2 M916_1.P2
N$19: M916_1.H1 M916_1.L2
N$20: M916_2.R2 M916_2.S2
N$21: M916_1.D2 M916_1.E2
N$22: IC16.1(A:I) M916_1.T2
N$23: IC15.9(D:I) M916_1.F2
N$24: IC120.8(B:O) M916_11.K2
N$25: M916_1.R2 M916_1.V2
N$26: M916_1.S1 M916_1.S2
N$28: IC72.2(A:I1) IC109.12(A:O)
N$29: M916_11.D2 M916_11.E2
N$30: IC113.13(F:I) M916_11.F2
N$31: IC20.9(B:I0) IC20.10(B:I1) IC113.12(F:O)
N$32: IC78.8(C:O) IC123.5(C:I)
N$33: IC7.10(B:PRE) IC66.6(A:O)
N$34: IC124.5(C:I) ; also sheet 2
N$35: IC8.9(B:I0) IC104.8(1Y)
N$36: IC94.12(F:O) IC116.2(A:D)
N$37: M916_11.R2 M916_11.S2
N$38: IC117.3(A:O) IC117.12(D:I0)
N$39: IC117.6(B:O) IC117.13(D:I1)
N$42: IC106.6(B:O) IC106.12(D:I0)
N$43: IC18.3(A:O) IC18.12(D:I0)
N$44: IC72.13(B:I3) IC106.11(D:O)
N$45: IC18.8(C:O) IC18.13(D:I1)
N$46: IC8.12(B:I2) IC11.11(D:O)
N$47: IC68.8(C:O) IC94.13(F:I)
N$48: IC71.6(A:O) IC107.4(B:I0)
N$49: IC68.10(C:I1) IC70.8(B:O)
N$50: IC110.12(A:O) IC118.12(D:I0)
N$51: IC72.8(B:O) IC108.4(B:I1)
N$52: IC107.6(B:O) IC108.3(B:I0)
N$53: IC118.6(B:O) IC118.13(D:I1)
N$54: IC106.3(A:O) IC108.5(B:I2)
N$55: IC68.9(C:I0) IC70.6(A:O)
N$56: IC2.6(B:O) IC68.11(C:I2)
N$58: IC15.11(E:I) IC61.6(B:O)
N$59: IC107.11(D:O) IC112.13(F:I)
N$60: IC72.1(A:I0) IC108.8(C:O)
N$61: IC72.4(A:I2) IC110.6(B:O)
N$62: IC71.8(B:O) IC72.5(A:I3)
N$63: IC74.10(B:PRE) IC78.3(A:O)
N$64: IC17.8(C:O) IC65.4(A:I2) IC65.5(A:I3)
N$65: IC107.8(C:O) IC107.12(D:I0)
N$66: IC17.3(A:O) IC65.1(A:I0) IC65.2(A:I1)
N$67: IC134.8(O) ; also sheet 2
N$70: IC2.9(C:I0) IC68.6(B:O)
N$71: IC78.6(B:O) IC113.11(E:I)
N$72: IC2.11(C:I2) IC68.12(A:O)
N$73: IC60.6(B:O) IC63.10(B:PRE)
N$76: IC115.11(B:CLK) IC119.3(A:O)
N$77: IC2.8(C:O) IC65.9(B:I0)
N$78: IC65.13(B:I3) IC113.10(E:O)
N$79: IC112.6(C:O) IC115.10(B:PRE)
N$80: IC8.13(B:I3) M916_14.U2
N$81: IC108.12(A:O) IC112.5(C:I)
N$82: IC69.8(C:O) IC123.1(A:I)
N$83: IC5.12(B:D) IC8.8(B:O)
N$84: IC11.3(A:O) IC11.4(B:I0)
N$85: IC11.2(A:I1) IC11.6(B:O) IC78.12(D:I0)
N$86: IC69.13(A:I2) IC78.11(D:O)
N$91: IC60.11(D:O) IC64.4(A:PRE)
N$92: IC59.11(D:O) IC62.10(B:PRE)
N$93: IC127.3(A:K) IC127.14(A:J) IC130.6(2Y)
N$94: IC127.7(B:J) IC127.10(B:K) IC130.8(1Y)
N$95: IC128.3(A:K) IC128.14(A:J) IC132.8(1Y)
N$96: IC129.3(A:K) IC129.14(A:J) IC131.6(2Y)
N$97: IC59.3(A:O) IC62.4(A:PRE)
N$99: IC129.7(B:J) IC129.10(B:K) IC132.6(2Y)
N$100: IC128.7(B:J) IC128.10(B:K) IC131.8(1Y)
N$101: IC124.4(B:O) IC127.5(B:CLK) IC128.5(B:CLK) IC129.5(B:CLK)
N$103: IC123.10(E:O) IC127.1(A:CLK) IC128.1(A:CLK) IC129.1(A:CLK)
N$104: IC97.8(1Y) IC101.10(B:PRE)
N$105: IC4.9(D:I) IC8.6(A:O)
N$106: IC4.8(D:O) IC9.13(B:I3)
N$107: IC6.12(B:D) IC9.8(B:O)
N$108: IC103.8(1Y) IC123.11(E:I)
N$109: IC105.6(2Y) IC124.3(B:I)
N$111: IC10.13(B:I3) IC124.2(A:O)
N$112: IC59.6(B:O) IC64.10(B:PRE)
N$113: IC59.8(C:O) IC63.4(A:PRE)
N$114: IC10.8(B:O) IC15.13(F:I)
N$115: IC118.8(C:O) IC124.1(A:I)
N$116: IC113.1(A:I) IC118.3(A:O)
N$117: IC109.6(B:O) ; also sheet 2
N$118: IC106.8(C:O) ; also sheet 2
N$119: IC112.11(E:I) IC117.8(C:O)
N$123: M916_3.D2 M916_3.J2 SV7.10
N$124: IC4.11(E:I) IC12.11(D:O)
N$125: IC7.2(A:D) IC12.6(B:O)
N$126: M916_3.E2 M916_3.K2 SV7.12
N$127: M916_12.D2 M916_12.J2 SV7.22
N$128: IC4.10(E:O) IC7.3(A:CLK)
N$129: IC99.6(2Y) IC102.10(B:PRE)
N$130: M916_12.E2 M916_12.K2 SV7.24
N$131: M916_4.D2 M916_4.J2 SV7.32
N$132: IC4.12(F:O) IC6.4(A:PRE)
N$133: M916_4.E2 M916_4.K2 SV6.6
N$134: M916_13.D2 M916_13.J2 SV6.12
N$135: M916_13.E2 M916_13.K2 SV6.14
N$136: M916_5.D2 M916_5.J2 SV6.22
N$137: IC4.13(F:I) IC13.6(B:O)
N$138: IC9.6(A:O) IC13.5(B:I1)
N$139: IC13.3(A:O) IC13.4(B:I0)
N$140: M916_5.E2 M916_5.K2 SV6.24
N$142: IC98.8(1Y) IC102.4(A:PRE)
N$146: IC97.6(2Y) IC100.4(A:PRE)
N$147: IC99.8(1Y) IC100.10(B:PRE)
N$148: IC98.6(2Y) IC101.4(A:PRE)
N$153: IC11.8(C:O) IC12.2(A:I1)
N$155: IC105.8(1Y) IC114.12(B:D)
N$161: IC10.6(A:O) IC14.1(A:I)
N$162: IC13.10(C:I1) IC13.12(D:I0) IC14.2(A:O)
N$185: IC103.6(2Y) IC114.2(A:D)
N$193: IC104.6(2Y) IC115.2(A:D)
NC: M916_3.H2 M916_3.L2 M916_3.M2 M916_4.H2 M916_4.L2 M916_4.M2 M916_5.H2 M916_5.L2 M916_5.M2 M916_8.A2 M916_8.B2 M916_8.J2 M916_10.D1 M916_12.H2 M916_12.L2 M916_12.M2 M916_13.H2 M916_13.L2 M916_13.M2 M916_15.R2 SV3.NN SV3.TT SV4.L SV4.NN SV4.R SV4.TT SV10.NN SV10.TT SV11.L SV11.NN SV11.R SV11.TT ; also sheet 2
PAR: IC7.6(A:Q\) M916_9.T1
PAR\: IC7.5(A:Q) IC13.13(D:I1) IC39.8(C:I0)
PC+ES: IC13.8(C:O) IC14.9(D:I)
PC+ES\: IC14.8(D:O) IC69.5(B:I2)
PWR_CLR: IC93.12(F:O)
PWR_CLR\: IC12.1(A:I0) IC12.10(C:I1) IC13.9(C:I0) IC61.5(B:I1) IC91.6(B:O) IC93.13(F:I) IC107.13(D:I1) IC116.4(A:PRE) IC116.13(B:CLR) IC137.1(A:CLR) IC137.13(B:CLR) M916_7.M1
RD+WD: IC9.4(A:I2) IC60.8(C:O) IC71.9(B:I0) IC109.2(A:I1)
RD_EN: IC106.5(B:I1) IC107.3(A:O)
RD_EN_LPB_00-02: IC103.1(1A) IC113.2(A:O) IC130.5(2D) IC131.5(2D) IC132.10(1E)
RD_EN_LPB_03-05: IC105.2(2A) IC112.10(E:O) IC130.10(1E) IC131.10(1E) IC132.5(2D)
RDD_00: IC63.12(B:D) IC130.4(2C) IC130.9(1D) M916_5.U2
RDD_00\: M916_5.V2
RDD_01: IC64.2(A:D) IC131.9(1D) IC132.9(1D) M916_13.U2
RDD_01\: M916_13.V2
RDD_02: IC62.12(B:D) IC131.4(2C) IC132.4(2C) M916_4.U2
RDD_02\: M916_4.V2
RDMK: M916_12.U2 M916_18.S2
RDMK\: M916_12.V2
READ_ALL: IC126.2(A:O)
READ_ALL\: IC106.13(D:I1) IC125.4 IC126.1(A:I)
READ_DATA: IC12.4(B:I0) IC106.4(B:I0) IC124.12(F:O)
READ_DATA\: IC60.9(C:I0) IC69.1(A:I0) IC124.13(F:I) IC125.3
RSTA: IC55.12(F:O)
RSTA\: IC31.3(A:I1) IC31.6(B:I1) IC31.9(C:I1) IC31.12(D:I1) IC32.3(A:I1) IC32.6(B:I1) IC32.9(C:I1) IC32.12(D:I1) IC33.3(A:I1) IC33.6(B:I1) IC55.13(F:I) IC87.6(B:O)
RSTB: IC88.8(D:O)
RSTB\: IC33.9(C:I1) IC33.12(D:I1) IC39.3(A:I1) IC39.6(B:I1) IC39.9(C:I1) IC39.12(D:I1) IC40.3(A:I1) IC40.6(B:I1) IC40.9(C:I1) IC40.12(D:I1) IC88.9(D:I) IC89.11(D:O)
SE: IC126.10(E:O)
SE\: IC8.10(B:I1) IC125.8 IC126.11(E:I)
SEARCH: IC106.1(A:I0) IC124.10(E:O)
SEARCH\: IC48.2(A:I0) IC69.2(A:I1) IC124.11(E:I) IC125.2
SEL: IC5.9(B:Q) M916_9.S1
SEL\: IC5.8(B:Q\) IC10.5(A:I3) IC39.5(B:I0)
SH_DTB: IC13.2(A:I1) IC62.3(A:CLK) IC62.11(B:CLK) IC63.3(A:CLK) IC63.11(B:CLK) IC64.3(A:CLK) IC64.11(B:CLK) IC65.6(A:O) IC100.3(A:CLK) IC100.11(B:CLK) IC101.3(A:CLK) IC101.11(B:CLK) IC102.3(A:CLK) IC102.11(B:CLK)
SH_EN: IC15.4(B:O) IC17.2(A:I1) IC103.2(2A) IC104.2(2A) IC105.1(1A)
SH_EN\: IC15.3(B:I) IC18.11(D:O) IC103.4(2C) IC104.4(2C) IC105.9(1D)
SH_ST: IC113.5(C:I) M916_18.M1
SH_ST-B: IC121.8(B:O) M916_17.C1
SHIFT_CK: IC123.2(A:O) M916_17.R2
SKP_RQ\: IC18.6(B:O) IC46.8(C:I0)
SP_DY\: IC115.12(B:D) ; also sheet 2
ST_BLK_MK: IC111.5(C:I) M916_10.K1 M916_18.R2
ST_BLK_MK\: IC9.1(A:I0) IC9.9(B:I0) IC111.6(C:O)
ST_CK: IC12.12(D:I0) IC111.9(D:I) M916_10.P1 M916_17.R1 ; also sheet 2
ST_CK\: IC111.8(D:O) IC121.2(A:I1)
ST_CK_0P: IC71.13(B:I3) IC94.10(E:O) IC109.13(A:I2)
ST_CK_0P\: IC94.11(E:I) ; also sheet 2
ST_DATA: IC70.1(A:I0) IC111.11(E:I) IC121.6(A:O)
ST_DATA\: IC111.10(E:O)
ST_FINAL: IC10.10(B:I1) IC91.12(D:I0) IC111.13(F:I) M916_10.N1 M916_17.L2
ST_FINAL\: IC107.2(A:I1) IC111.12(F:O) IC121.4(A:I2)
ST_IDLE: IC112.1(A:I) M916_10.R1 M916_17.D2
ST_IDLE\: IC9.2(A:I1) IC9.10(B:I1) IC112.2(A:O)
ST_REV_CK: IC68.5(B:I2) IC91.9(C:I0) IC111.1(A:I) M916_10.L1 M916_17.S1 ; also sheet 2
ST_REV_CK\: IC111.2(A:O)
SWTM: IC2.4(B:I1) IC55.1(A:I) IC55.8(D:O) IC104.10(1E) IC110.2(A:I1) IC118.4(B:I0) M916_10.V2
SWTM\: IC55.2(A:O) IC104.12(1B)
SYNC: IC66.9(B:I0) IC66.10(B:I1) M916_17.N2
SYNC-P\: IC66.8(B:O) IC73.1(A:CLR) IC73.13(B:CLR) IC74.1(A:CLR) IC74.13(B:CLR) IC75.1(A:CLR) IC75.13(B:CLR)
SYNC\: M916_17.M2
SYNC_EN: IC69.12(A:O) M916_17.H1
T3: IC123.12(F:O) ; also sheet 2
T_00\: M916_8.V2 M916_15.V2 M916_16.V2
T_01\: M916_7.S1 M916_8.M2 M916_16.M2
T_02\: M916_7.H2 M916_8.N2 M916_16.N2
T_03\: M916_7.J2 M916_8.P2 M916_16.P2
T_04\: M916_7.N2 M916_8.R2 M916_16.R2
T_05\: M916_7.P2 M916_8.S2 M916_16.S2
T_06\: M916_7.U2 M916_8.T2 M916_16.T2
T_07\: M916_7.V2 M916_8.U2 M916_16.U2
T_FWD\: M916_7.K1 M916_8.E2 M916_16.H2
T_GO\: M916_7.D1 M916_8.C2 M916_16.D2
T_PWR_CLR\: M916_7.R1 M916_8.H2 M916_16.K2
T_REV\: M916_7.L1 M916_8.F2 M916_16.J2
T_SINGLE_UNIT\: M916_8.K2 M916_14.T2
T_STOP\: M916_7.E1 M916_8.D2 M916_16.E2
T_TRK: IC61.13(D:I1) IC119.2(A:I1) M916_3.U2 ; also sheet 2
T_TRK\: IC61.10(C:I1) M916_3.V2
T_WRITE_OK\: M916_6.H2 M916_8.L2 M916_16.L2
TIM: IC6.5(A:Q) M916_9.U1
TIM\: IC6.6(A:Q\) IC10.2(A:I1) IC39.11(D:I0)
TM_EN: IC112.3(B:I) IC118.11(D:O) IC120.9(B:I0) IC122.1(A:I0) M916_3.R2 M916_12.R2
TM_EN\: IC61.9(C:I0) IC61.12(D:I0) IC108.13(A:I2) IC109.10(C:I1) IC112.4(B:O) ; also sheet 2
TP00: IC5.3(A:CLK) IC19.8(B:O) IC66.2(A:I1) IC66.12(B:I2) IC66.13(B:I3) IC73.3(A:CLK) IC73.11(B:CLK) IC74.3(A:CLK) IC78.2(A:I1) IC117.5(B:I1) M916_2.M2 M916_2.N2 M916_2.P2
TP00\: IC19.6(A:O) IC19.9(B:I0) IC19.10(B:I1) IC19.12(B:I2) IC19.13(B:I3) IC75.3(A:CLK) M916_18.N1
TP00_A: IC20.6(A:O) IC65.10(B:I1) IC109.4(B:I1)
TP00_A\: IC20.1(A:I0) IC20.2(A:I1) IC20.4(A:I2) IC20.5(A:I3) M916_2.L2
TP0_XTLK_DY\: IC15.8(D:O) IC20.12(B:I2) M916_2.J2 M916_2.K2
TP01: IC17.10(C:I1) IC21.6(A:O) IC106.10(C:I1) IC117.2(A:I1) M916_11.M2 M916_11.N2 M916_11.P2 M916_17.F1
TP01\: IC20.8(B:O) IC21.1(A:I0) IC21.2(A:I1) IC21.4(A:I2) IC21.5(A:I3) IC74.11(B:CLK)
TP01_A: IC21.8(B:O) IC72.12(B:I2) IC118.10(C:I1)
TP01_A\: IC21.9(B:I0) IC21.10(B:I1) IC21.12(B:I2) IC21.13(B:I3) M916_11.L2
TP1_XTLK_DY\: IC16.2(A:O) IC19.2(A:I1) M916_11.H2 M916_11.J2
TS03\: IC89.3(A:O) ; also sheet 2
U+M_DY\: IC108.1(A:I0) IC110.13(A:I2) ; also sheet 2
USR_00: IC1.22(B) IC56.12(A:Q) M916_9.A1
USR_00\: IC31.2(A:I0) IC56.13(A:Q\)
USR_01: IC1.21(C) IC56.9(B:Q) M916_9.B1
USR_01\: IC31.5(B:I0) IC56.8(B:Q\)
USR_02: IC1.20(D) IC57.12(A:Q) M916_9.C1
USR_02\: IC31.8(C:I0) IC57.13(A:Q\)
USR_02_: IC1.18(G1) IC1.19(G2) IC2.12(A:O)
UTS: IC11.5(B:I1) IC78.9(C:I0) IC115.8(B:Q\) M916_10.J1
UTS\: IC67.9(B:I0) IC67.10(B:I1) IC67.12(B:I2) IC67.13(B:I3) IC109.11(C:I2) IC115.9(B:Q) IC119.1(A:I0) IC120.1(A:I0) IC120.2(A:I1) IC120.4(A:I2) IC120.5(A:I3)
VCC: IC97.11(1F) IC97.13(1C) IC98.11(1F) IC98.13(1C) IC99.11(1F) IC99.13(1C) IC103.11(1F) IC103.13(1C) IC104.11(1F) IC104.13(1C) IC105.11(1F) IC105.13(1C) IC130.11(1F) IC130.13(1C) IC131.11(1F) IC131.13(1C) IC132.11(1F) IC132.13(1C) M916_1.A2 M916_2.A2 M916_3.A2 M916_4.A2 M916_5.A2 M916_6.A2 M916_7.A2 M916_11.A2 M916_12.A2 M916_13.A2 M916_14.A2 M916_15.A2 M916_17.A2 M916_18.A2 ; also sheet 2
W01: M916_10.J2 M916_17.J2
W01-W05: M916_18.K1
W02: M916_10.K2 M916_17.V2
W03: M916_10.L2 M916_17.E2
W04: M916_10.M2 M916_18.T2
W05: M916_10.N2 M916_17.U2
W06: M916_10.P2 M916_18.M2
W07: M916_10.R2 M916_18.K2
W08: M916_10.S2 M916_18.L1
W09: M916_10.T2 M916_17.F2
W+UTS: IC19.1(A:I0) IC20.13(B:I3) IC109.8(C:O)
W-INH: IC7.8(B:Q\)
W-INH\: IC7.9(B:Q) IC68.2(A:I1) IC70.10(B:I1)
WB00: IC114.6(A:Q\) IC130.2(2A) M916_5.N2 M916_9.P2 M916_12.N2
WB00\: IC103.5(2D) IC114.5(A:Q) M916_5.P2 M916_12.P2
WB01: IC114.8(B:Q\) IC132.1(1A) M916_9.R2 M916_13.N2
WB01\: IC105.10(1E) IC114.9(B:Q) M916_13.P2
WB02: IC115.6(A:Q\) IC131.2(2A) M916_4.N2 M916_9.S2
WB02\: IC104.5(2D) IC115.5(A:Q) M916_4.P2
WC: IC66.1(A:I0) IC68.1(A:I0) M916_10.H1 ; also sheet 2
WC0: IC79.8(C:O) IC93.9(D:I)
WC0\: IC93.8(D:O) ; also sheet 2
WC\: IC71.12(B:I2) IC110.3(B:I0) ; also sheet 2
WR_EN: IC103.10(1E) IC105.5(2D) IC109.3(B:I0) IC116.6(A:Q\) IC117.1(A:I0) IC118.5(B:I1) IC130.3(2B) IC130.12(1B) IC131.3(2B) IC131.12(1B) IC132.3(2B) IC132.12(1B) M916_4.R2 M916_5.R2 M916_10.F1 M916_13.R2
WR_EN\: IC2.10(C:I1) IC106.9(C:I0) IC109.9(C:I0) IC116.5(A:Q) IC117.9(C:I0) IC118.1(A:I0)
WRITE_ALL: IC7.11(B:CLK) IC68.13(A:I2) IC70.9(B:I0) IC126.6(C:O)
WRITE_ALL\: IC125.6 IC126.5(C:I)
WRITE_DATA: IC10.9(B:I0) IC68.4(B:I1) IC70.2(A:I1) IC71.4(A:I2) IC126.4(B:O)
WRITE_DATA\: IC60.10(C:I1) IC125.5 IC126.3(B:I)
WRITE_OK: IC2.5(B:I2) IC78.10(C:I1) IC123.3(B:I) M916_6.D2
WRITE_OK+UTS: IC70.5(A:I3) IC70.13(B:I3) IC123.6(C:O)
WRITE_OK\: IC11.13(D:I1) IC123.4(B:O)
WRTM: IC2.3(B:I0) IC104.1(1A) IC110.1(A:I0) IC126.8(D:O)
WRTM+FR03: IC60.3(A:O) IC108.11(C:I2) IC110.5(B:I2)
WRTM\: IC60.1(A:I0) IC104.9(1D) IC125.7 IC126.9(D:I)
XOR_TO_LPB: IC103.9(1D) IC103.12(1B) IC105.3(2B) IC105.4(2C) ; also sheet 2
XSA_DY: IC5.11(B:CLK) IC76.3(A:CLK) IC76.11(B:CLK) IC124.6(C:O)
XSAD: IC9.5(A:I3) IC14.12(F:O)
XSAD\: IC14.13(F:I) ; also sheet 2
XSTA: IC56.1(A:CLK) IC56.5(B:CLK) IC57.1(A:CLK) IC57.5(B:CLK) IC58.1(A:CLK) IC58.5(B:CLK) IC88.4(B:O) IC95.1(A:CLK) IC95.5(B:CLK) IC96.1(A:CLK) IC96.5(B:CLK) ; also sheet 2
XSTA\: IC61.2(A:I1) IC87.11(D:O) IC88.3(B:I) ; also sheet 2
Unconnected: IC1.9 IC1.10 IC1.11 IC1.13 IC1.14 IC1.15 IC1.16 IC1.17 IC48.4(B:O) IC48.5(B:I0) IC48.6(B:I1) IC48.8(C:I0) IC48.9(C:I1) IC48.10(C:O) IC48.11(D:I0) IC48.12(D:I1) IC48.13(D:O) IC53.5(B:O) IC53.6(B:I0) IC53.7(B:I1) IC119.4(B:I0) IC119.5(B:I1) IC119.6(B:O) IC119.8(C:O) IC119.9(C:I0) IC119.10(C:I1) IC119.11(D:O) IC119.12(D:I0) IC119.13(D:I1) IC122.8(B:O) IC122.9(B:I0) IC122.10(B:I1) IC122.12(B:I2) IC122.13(B:I3) IC125.9 IC125.10 IC125.11 IC125.13 IC125.14 IC125.15 IC125.16 IC125.17 IC136.3(B:I) IC136.4(B:O) IC136.5(C:I) IC136.6(C:O) IC136.8(D:O) IC136.9(D:I) IC136.10(E:O) IC136.11(E:I) IC136.12(F:O) IC136.13(F:I) M916_1.A1 M916_1.B1 M916_1.B2 M916_1.C1 M916_1.D1 M916_1.E1 M916_1.F1 M916_1.J1 M916_1.K1 M916_1.L1 M916_1.M1 M916_1.N1 M916_1.P1 M916_1.R1 M916_1.U1 M916_1.U2 M916_1.V1 M916_2.A1 M916_2.B1 M916_2.B2 M916_2.C1 M916_2.D1 M916_2.E1 M916_2.F1 M916_2.H1 M916_2.J1 M916_2.K1 M916_2.L1 M916_2.M1 M916_2.N1 M916_2.P1 M916_2.R1 M916_2.S1 M916_2.T2 M916_2.U1 M916_2.U2 M916_2.V1 M916_2.V2 M916_3.A1 M916_3.B1 M916_3.C1 M916_3.D1 M916_3.E1 M916_3.F1 M916_3.F2 M916_3.H1 M916_3.J1 M916_3.K1 M916_3.L1 M916_3.M1 M916_3.N1 M916_3.P1 M916_3.R1 M916_3.S1 M916_3.S2 M916_3.T1 M916_3.T2 M916_3.U1 M916_3.V1 M916_4.A1 M916_4.B1 M916_4.C1 M916_4.D1 M916_4.E1 M916_4.F1 M916_4.F2 M916_4.H1 M916_4.J1 M916_4.K1 M916_4.L1 M916_4.M1 M916_4.N1 M916_4.P1 M916_4.R1 M916_4.S1 M916_4.S2 M916_4.T1 M916_4.T2 M916_4.U1 M916_4.V1 M916_5.A1 M916_5.B1 M916_5.C1 M916_5.D1 M916_5.E1 M916_5.F1 M916_5.F2 M916_5.H1 M916_5.J1 M916_5.K1 M916_5.L1 M916_5.M1 M916_5.N1 M916_5.P1 M916_5.R1 M916_5.S1 M916_5.S2 M916_5.T1 M916_5.T2 M916_5.U1 M916_5.V1 M916_6.A1 M916_6.B1 M916_6.C1 M916_6.D1 M916_6.E1 M916_6.E2 M916_6.F1 M916_6.F2 M916_6.H1 M916_6.J1 M916_6.J2 M916_6.K1 M916_6.K2 M916_6.L1 M916_6.L2 M916_6.M1 M916_6.N1 M916_6.N2 M916_6.P1 M916_6.P2 M916_6.R1 M916_6.R2 M916_6.S1 M916_6.S2 M916_6.T1 M916_6.T2 M916_6.U1 M916_6.U2 M916_6.V1 M916_6.V2 M916_8.A1 M916_8.B1 M916_8.C1 M916_8.D1 M916_8.E1 M916_8.F1 M916_8.H1 M916_8.J1 M916_8.K1 M916_8.L1 M916_8.M1 M916_8.N1 M916_8.P1 M916_8.R1 M916_8.S1 M916_8.T1 M916_8.U1 M916_8.V1 M916_11.A1 M916_11.B1 M916_11.B2 M916_11.C1 M916_11.D1 M916_11.E1 M916_11.F1 M916_11.H1 M916_11.J1 M916_11.K1 M916_11.L1 M916_11.M1 M916_11.N1 M916_11.P1 M916_11.R1 M916_11.S1 M916_11.T2 M916_11.U1 M916_11.U2 M916_11.V1 M916_11.V2 M916_12.A1 M916_12.B1 M916_12.C1 M916_12.D1 M916_12.E1 M916_12.F1 M916_12.F2 M916_12.H1 M916_12.J1 M916_12.K1 M916_12.L1 M916_12.M1 M916_12.N1 M916_12.P1 M916_12.R1 M916_12.S1 M916_12.S2 M916_12.T1 M916_12.T2 M916_12.U1 M916_12.V1 M916_13.A1 M916_13.B1 M916_13.C1 M916_13.D1 M916_13.E1 M916_13.F1 M916_13.F2 M916_13.H1 M916_13.J1 M916_13.K1 M916_13.L1 M916_13.M1 M916_13.N1 M916_13.P1 M916_13.R1 M916_13.S1 M916_13.S2 M916_13.T1 M916_13.T2 M916_13.U1 M916_13.V1 M916_14.A1 M916_14.B1 M916_14.C1 M916_14.D1 M916_14.D2 M916_14.E1 M916_14.E2 M916_14.F1 M916_14.F2 M916_14.H1 M916_14.H2 M916_14.J1 M916_14.J2 M916_14.K1 M916_14.K2 M916_14.L1 M916_14.L2 M916_14.M1 M916_14.M2 M916_14.N1 M916_14.N2 M916_14.P1 M916_14.P2 M916_14.R1 M916_14.R2 M916_14.S1 M916_14.S2 M916_14.T1 M916_14.U1 M916_14.V1 M916_14.V2 M916_15.A1 M916_15.B1 M916_15.C1 M916_15.D1 M916_15.D2 M916_15.E1 M916_15.E2 M916_15.F1 M916_15.F2 M916_15.H1 M916_15.H2 M916_15.J1 M916_15.J2 M916_15.K1 M916_15.K2 M916_15.L1 M916_15.L2 M916_15.M1 M916_15.M2 M916_15.N1 M916_15.N2 M916_15.P1 M916_15.P2 M916_15.R1 M916_15.S1 M916_15.U2 M916_16.A1 M916_16.A2 M916_16.B1 M916_16.C1 M916_16.D1 M916_16.E1 M916_16.F1 M916_16.F2 M916_16.H1 M916_16.J1 M916_16.K1 M916_16.L1 M916_16.M1 M916_16.N1 M916_16.P1 M916_16.R1 M916_16.S1 M916_16.T1 M916_16.U1 M916_16.V1 M916_17.A1 M916_17.B1 M916_17.B2 M916_17.D1 M916_17.E1 M916_17.J1 M916_17.K1 M916_17.L1 M916_17.M1 M916_17.N1 M916_17.P1 M916_18.A1 M916_18.B1 M916_18.B2 M916_18.C1 M916_18.D1 M916_18.E1 M916_18.L2 M916_18.N2 M916_18.P1 M916_18.R1 M916_18.S1 M916_18.U1 M916_18.V1 SV6.2 SV6.4 SV6.16 SV6.26 SV6.28 SV6.30 SV6.32 SV6.34 SV7.2 SV7.4 SV7.6 SV7.8 SV7.18 SV7.20

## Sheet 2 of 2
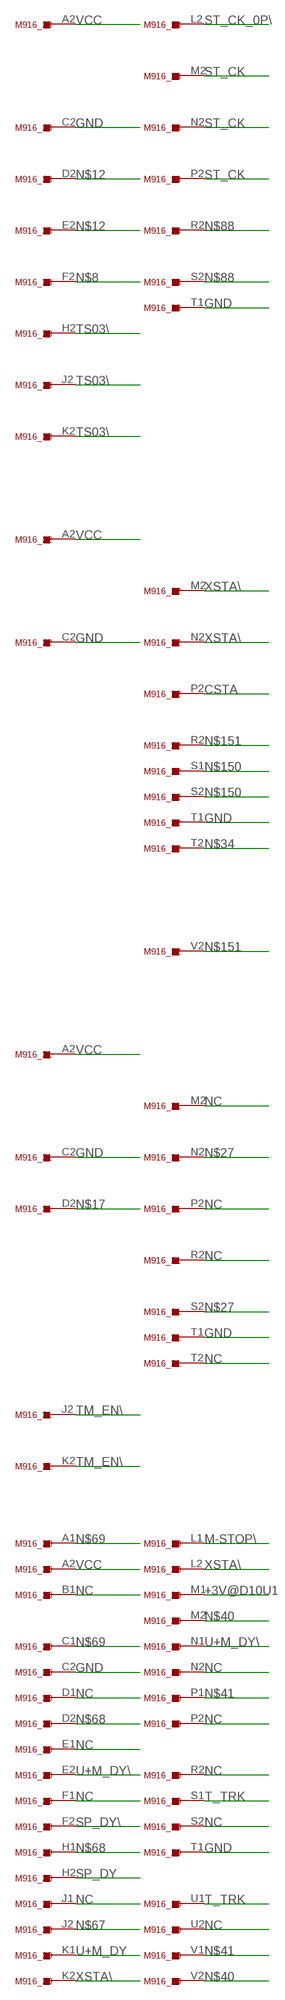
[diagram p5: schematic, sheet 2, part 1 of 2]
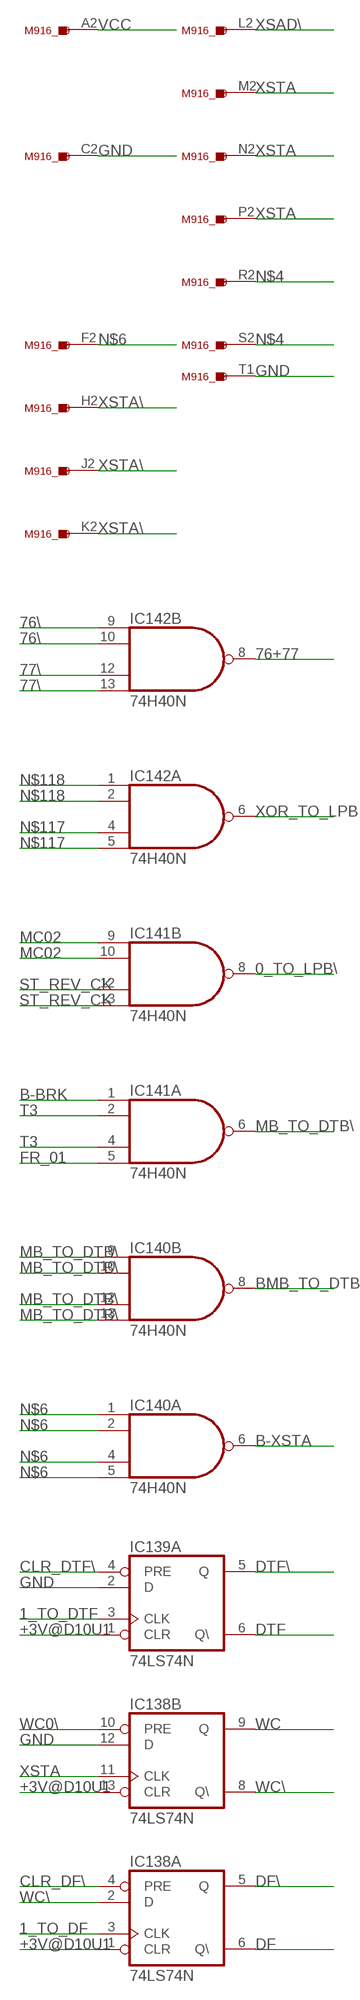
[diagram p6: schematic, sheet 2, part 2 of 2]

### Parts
IC138  74LS74N  [DIL14]
IC139  74LS74N  [DIL14]
IC140  74H40N  74S20N  [DIL14]
IC141  74H40N  74S20N  [DIL14]
IC142  74H40N  74S20N  [DIL14]
M916_19  M602  M916  [H807]
M916_20  M307  M916  [H807]
M916_21  M401  M916  [H807]
M916_22  M302  M916  [H807]
M916_23  M602  M916  [H807]

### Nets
0_TO_LPB\: IC141.8(B:O) ; also sheet 1
1_TO_DF: IC138.3(A:CLK) ; also sheet 1
1_TO_DTF: IC139.3(A:CLK) ; also sheet 1
76+77: IC142.8(B:O) ; also sheet 1
76\: IC142.9(B:I0) IC142.10(B:I1) ; also sheet 1
77\: IC142.12(B:I2) IC142.13(B:I3) ; also sheet 1
+3V@D10U1: IC138.1(A:CLR) IC138.13(B:CLR) IC139.1(A:CLR) M916_20.M1 ; also sheet 1
B-BRK: IC141.1(A:I0) ; also sheet 1
B-XSTA: IC140.6(A:O) ; also sheet 1
BMB_TO_DTB: IC140.8(B:O) ; also sheet 1
CLR_DF\: IC138.4(A:PRE) ; also sheet 1
CLR_DTF\: IC139.4(A:PRE) ; also sheet 1
CSTA: M916_22.P2 ; also sheet 1
DF: IC138.6(A:Q\) ; also sheet 1
DF\: IC138.5(A:Q) ; also sheet 1
DTF: IC139.6(A:Q\) ; also sheet 1
DTF\: IC139.5(A:Q) ; also sheet 1
FR_01: IC141.5(A:I3) ; also sheet 1
GND: IC138.12(B:D) IC139.2(A:D) M916_19.C2 M916_19.T1 M916_20.C2 M916_20.T1 M916_21.C2 M916_21.T1 M916_22.C2 M916_22.T1 M916_23.C2 M916_23.T1 ; also sheet 1
M-STOP\: M916_20.L1 ; also sheet 1
MB_TO_DTB\: IC140.9(B:I0) IC140.10(B:I1) IC140.12(B:I2) IC140.13(B:I3) IC141.6(A:O)
MC02: IC141.9(B:I0) IC141.10(B:I1) ; also sheet 1
N$4: M916_19.R2 M916_19.S2
N$6: IC140.1(A:I0) IC140.2(A:I1) IC140.4(A:I2) IC140.5(A:I3) M916_19.F2
N$8: M916_23.F2 ; also sheet 1
N$12: M916_23.D2 M916_23.E2
N$17: M916_21.D2 ; also sheet 1
N$27: M916_21.N2 M916_21.S2
N$34: M916_22.T2 ; also sheet 1
N$40: M916_20.M2 M916_20.V2
N$41: M916_20.P1 M916_20.V1
N$67: M916_20.J2 ; also sheet 1
N$68: M916_20.D2 M916_20.H1
N$69: M916_20.A1 M916_20.C1
N$88: M916_23.R2 M916_23.S2
N$117: IC142.4(A:I2) IC142.5(A:I3) ; also sheet 1
N$118: IC142.1(A:I0) IC142.2(A:I1) ; also sheet 1
N$150: M916_22.S1 M916_22.S2
N$151: M916_22.R2 M916_22.V2
NC: M916_20.B1 M916_20.D1 M916_20.E1 M916_20.F1 M916_20.J1 M916_20.N2 M916_20.P2 M916_20.R2 M916_20.S2 M916_20.U2 M916_21.M2 M916_21.P2 M916_21.R2 M916_21.T2 ; also sheet 1
SP_DY: M916_20.H2
SP_DY\: M916_20.F2 ; also sheet 1
ST_CK: M916_23.M2 M916_23.N2 M916_23.P2 ; also sheet 1
ST_CK_0P\: M916_23.L2 ; also sheet 1
ST_REV_CK: IC141.12(B:I2) IC141.13(B:I3) ; also sheet 1
T3: IC141.2(A:I1) IC141.4(A:I2) ; also sheet 1
T_TRK: M916_20.S1 M916_20.U1 ; also sheet 1
TM_EN\: M916_21.J2 M916_21.K2 ; also sheet 1
TS03\: M916_23.H2 M916_23.J2 M916_23.K2 ; also sheet 1
U+M_DY: M916_20.K1
U+M_DY\: M916_20.E2 M916_20.N1 ; also sheet 1
VCC: M916_19.A2 M916_20.A2 M916_21.A2 M916_22.A2 M916_23.A2 ; also sheet 1
WC: IC138.9(B:Q) ; also sheet 1
WC0\: IC138.10(B:PRE) ; also sheet 1
WC\: IC138.2(A:D) IC138.8(B:Q\) ; also sheet 1
XOR_TO_LPB: IC142.6(A:O) ; also sheet 1
XSAD\: M916_19.L2 ; also sheet 1
XSTA: IC138.11(B:CLK) M916_19.M2 M916_19.N2 M916_19.P2 ; also sheet 1
XSTA\: M916_19.H2 M916_19.J2 M916_19.K2 M916_20.K2 M916_20.L2 M916_22.M2 M916_22.N2 ; also sheet 1
Unconnected: IC139.8(B:Q\) IC139.9(B:Q) IC139.10(B:PRE) IC139.11(B:CLK) IC139.12(B:D) IC139.13(B:CLR) M916_19.A1 M916_19.B1 M916_19.B2 M916_19.C1 M916_19.D1 M916_19.D2 M916_19.E1 M916_19.E2 M916_19.F1 M916_19.H1 M916_19.J1 M916_19.K1 M916_19.L1 M916_19.M1 M916_19.N1 M916_19.P1 M916_19.R1 M916_19.S1 M916_19.T2 M916_19.U1 M916_19.U2 M916_19.V1 M916_19.V2 M916_20.B2 M916_20.R1 M916_20.T2 M916_21.A1 M916_21.B1 M916_21.B2 M916_21.C1 M916_21.D1 M916_21.E1 M916_21.E2 M916_21.F1 M916_21.F2 M916_21.H1 M916_21.H2 M916_21.J1 M916_21.K1 M916_21.L1 M916_21.L2 M916_21.M1 M916_21.N1 M916_21.P1 M916_21.R1 M916_21.S1 M916_21.U1 M916_21.U2 M916_21.V1 M916_21.V2 M916_22.A1 M916_22.B1 M916_22.B2 M916_22.C1 M916_22.D1 M916_22.D2 M916_22.E1 M916_22.E2 M916_22.F1 M916_22.F2 M916_22.H1 M916_22.H2 M916_22.J1 M916_22.J2 M916_22.K1 M916_22.K2 M916_22.L1 M916_22.L2 M916_22.M1 M916_22.N1 M916_22.P1 M916_22.R1 M916_22.U1 M916_22.U2 M916_22.V1 M916_23.A1 M916_23.B1 M916_23.B2 M916_23.C1 M916_23.D1 M916_23.E1 M916_23.F1 M916_23.H1 M916_23.J1 M916_23.K1 M916_23.L1 M916_23.M1 M916_23.N1 M916_23.P1 M916_23.R1 M916_23.S1 M916_23.T2 M916_23.U1 M916_23.U2 M916_23.V1 M916_23.V2

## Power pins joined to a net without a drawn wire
GND: IC1.12(GND) IC2.7(P:GND) IC3.7(P:GND) IC4.7(P:GND) IC5.7(P:GND) IC6.7(P:GND) IC7.7(P:GND) IC8.7(P:GND) IC9.7(P:GND) IC10.7(P:GND) IC11.7(P:GND) IC12.7(P:GND) IC13.7(P:GND) IC14.7(P:GND) IC15.7(P:GND) IC16.7(P:GND) IC17.7(P:GND) IC18.7(P:GND) IC19.7(P:GND) IC20.7(P:GND) IC21.7(P:GND) IC22.7(P:GND) IC23.7(P:GND) IC24.7(P:GND) IC25.4(P:GND) IC26.4(P:GND) IC27.4(P:GND) IC28.4(P:GND) IC29.4(P:GND) IC30.4(P:GND) IC31.7(P:GND) IC32.7(P:GND) IC33.7(P:GND) IC34.4(P:GND) IC35.4(P:GND) IC36.4(P:GND) IC37.4(P:GND) IC38.4(P:GND) IC39.7(P:GND) IC40.7(P:GND) IC41.4(P:GND) IC42.4(P:GND) IC43.4(P:GND) IC44.4(P:GND) IC45.4(P:GND) IC46.7(P:GND) IC47.7(P:GND) IC48.7(P:GND) IC49.4(P:GND) IC50.4(P:GND) IC51.4(P:GND) IC52.4(P:GND) IC53.4(P:GND) IC54.7(P:GND) IC55.7(P:GND) IC56.11(P:GND) IC57.11(P:GND) IC58.11(P:GND) IC59.7(P:GND) IC60.7(P:GND) IC61.7(P:GND) IC62.7(P:GND) IC63.7(P:GND) IC64.7(P:GND) IC65.7(P:GND) IC66.7(P:GND) IC67.7(P:GND) IC68.7(P:GND) IC69.7(P:GND) IC70.7(P:GND) IC71.7(P:GND) IC72.7(P:GND) IC73.7(P:GND) IC74.7(P:GND) IC75.7(P:GND) IC76.7(P:GND) IC77.7(P:GND) IC78.7(P:GND) IC79.7(P:GND) IC80.7(P:GND) IC81.7(P:GND) IC82.7(P:GND) IC83.7(P:GND) IC84.7(P:GND) IC85.7(P:GND) IC86.7(GND) IC87.7(P:GND) IC88.7(P:GND) IC89.7(P:GND) IC90.7(GND) IC91.7(P:GND) IC92.7(P:GND) IC93.7(P:GND) IC94.7(P:GND) IC95.11(P:GND) IC96.11(P:GND) IC97.7(GND) IC98.7(GND) IC99.7(GND) IC100.7(P:GND) IC101.7(P:GND) IC102.7(P:GND) IC103.7(GND) IC104.7(GND) IC105.7(GND) IC106.7(P:GND) IC107.7(P:GND) IC108.7(P:GND) IC109.7(P:GND) IC110.7(P:GND) IC111.7(P:GND) IC112.7(P:GND) IC113.7(P:GND) IC114.7(P:GND) IC115.7(P:GND) IC116.7(P:GND) IC117.7(P:GND) IC118.7(P:GND) IC119.7(P:GND) IC120.7(P:GND) IC121.7(P:GND) IC122.7(P:GND) IC123.7(P:GND) IC124.7(P:GND) IC125.12(GND) IC126.7(P:GND) IC127.11(P:GND) IC128.11(P:GND) IC129.11(P:GND) IC130.7(GND) IC131.7(GND) IC132.7(GND) IC133.7(GND) IC134.7(GND) IC135.7(GND) IC136.7(P:GND) IC137.7(P:GND) IC138.7(P:GND) IC139.7(P:GND) IC140.7(P:GND) IC141.7(P:GND) IC142.7(P:GND)
VCC: IC1.24(VCC) IC2.14(P:VCC) IC3.14(P:VCC) IC4.14(P:VCC) IC5.14(P:VCC) IC6.14(P:VCC) IC7.14(P:VCC) IC8.14(P:VCC) IC9.14(P:VCC) IC10.14(P:VCC) IC11.14(P:VCC) IC12.14(P:VCC) IC13.14(P:VCC) IC14.14(P:VCC) IC15.14(P:VCC) IC16.14(P:VCC) IC17.14(P:VCC) IC18.14(P:VCC) IC19.14(P:VCC) IC20.14(P:VCC) IC21.14(P:VCC) IC22.14(P:VCC) IC23.14(P:VCC) IC24.14(P:VCC) IC25.8(P:VCC) IC26.8(P:VCC) IC27.8(P:VCC) IC28.8(P:VCC) IC29.8(P:VCC) IC30.8(P:VCC) IC31.14(P:VCC) IC32.14(P:VCC) IC33.14(P:VCC) IC34.8(P:VCC) IC35.8(P:VCC) IC36.8(P:VCC) IC37.8(P:VCC) IC38.8(P:VCC) IC39.14(P:VCC) IC40.14(P:VCC) IC41.8(P:VCC) IC42.8(P:VCC) IC43.8(P:VCC) IC44.8(P:VCC) IC45.8(P:VCC) IC46.14(P:VCC) IC47.14(P:VCC) IC48.14(P:VCC) IC49.8(P:VCC) IC50.8(P:VCC) IC51.8(P:VCC) IC52.8(P:VCC) IC53.8(P:VCC) IC54.14(P:VCC) IC55.14(P:VCC) IC56.4(P:VCC) IC57.4(P:VCC) IC58.4(P:VCC) IC59.14(P:VCC) IC60.14(P:VCC) IC61.14(P:VCC) IC62.14(P:VCC) IC63.14(P:VCC) IC64.14(P:VCC) IC65.14(P:VCC) IC66.14(P:VCC) IC67.14(P:VCC) IC68.14(P:VCC) IC69.14(P:VCC) IC70.14(P:VCC) IC71.14(P:VCC) IC72.14(P:VCC) IC73.14(P:VCC) IC74.14(P:VCC) IC75.14(P:VCC) IC76.14(P:VCC) IC77.14(P:VCC) IC78.14(P:VCC) IC79.14(P:VCC) IC80.14(P:VCC) IC81.14(P:VCC) IC82.14(P:VCC) IC83.14(P:VCC) IC84.14(P:VCC) IC85.14(P:VCC) IC86.14(VCC) IC87.14(P:VCC) IC88.14(P:VCC) IC89.14(P:VCC) IC90.14(VCC) IC91.14(P:VCC) IC92.14(P:VCC) IC93.14(P:VCC) IC94.14(P:VCC) IC95.4(P:VCC) IC96.4(P:VCC) IC97.14(VCC) IC98.14(VCC) IC99.14(VCC) IC100.14(P:VCC) IC101.14(P:VCC) IC102.14(P:VCC) IC103.14(VCC) IC104.14(VCC) IC105.14(VCC) IC106.14(P:VCC) IC107.14(P:VCC) IC108.14(P:VCC) IC109.14(P:VCC) IC110.14(P:VCC) IC111.14(P:VCC) IC112.14(P:VCC) IC113.14(P:VCC) IC114.14(P:VCC) IC115.14(P:VCC) IC116.14(P:VCC) IC117.14(P:VCC) IC118.14(P:VCC) IC119.14(P:VCC) IC120.14(P:VCC) IC121.14(P:VCC) IC122.14(P:VCC) IC123.14(P:VCC) IC124.14(P:VCC) IC125.24(VCC) IC126.14(P:VCC) IC127.4(P:VCC) IC128.4(P:VCC) IC129.4(P:VCC) IC130.14(VCC) IC131.14(VCC) IC132.14(VCC) IC133.14(VCC) IC134.14(VCC) IC135.14(VCC) IC136.14(P:VCC) IC137.14(P:VCC) IC138.14(P:VCC) IC139.14(P:VCC) IC140.14(P:VCC) IC141.14(P:VCC) IC142.14(P:VCC)

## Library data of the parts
IC1 IC125 = 74xx-jameco:74*154: 4-line to 16-line data SELECTOR/MULTIPLEXER
IC2 IC68 IC69 IC108-IC110 = 74xx-jameco:74*10: Triple 3-input NAND gate
IC3 IC4 IC14-IC16 IC54 IC55 IC88 IC92-IC94 IC111-IC113 IC123 IC124 IC126 IC136 = 74xx-jameco:74*04: Hex INVERTER
IC5-IC7 IC62-IC64 IC73-IC77 IC100-IC102 IC114-IC116 IC137-IC139 = 74xx-jameco:74*74: Dual D type positive edge triggered FLIP FLOP, preset and clear
IC8-IC10 IC19-IC21 IC65-IC67 IC70-IC72 IC120-IC122 IC140-IC142 = 74xx-jameco:74*20: Dual 4-input NAND gate
IC11-IC13 IC17 IC18 IC59-IC61 IC78-IC85 IC87 IC89 IC91 IC106 IC107 IC117-IC119 = 74xx-jameco:74*00: Quad 2-input NAND gate
IC22-IC24 IC31-IC33 IC39 IC40 IC46-IC48 = 74xx-jameco:74*02: Quad 2-input NOR gate
IC25-IC30 IC34-IC38 IC41-IC45 IC49-IC53 = 74xx-jameco:DS75452: Quad 2-input NAND gate, open collector output
IC56-IC58 IC95 IC96 IC127-IC129 = 74xx-jameco:74*73: Dual J-K FLIP FLOP, clear
IC86 IC90 IC133-IC135 = 74xx-jameco:74*30: 8-input NAND gate
IC97-IC99 IC103-IC105 IC130-IC132 = 74xx-us:74*51: AND-OR-INVERT gates/for S-type see 74S51
M916_1-M916_23 = dec-m:M916: Simple 36 pin connector/wire cable
SV1-SV5 SV8-SV12 = dec-con:DEC40PIN: PIN HEADER
SV6 SV7 = con-lstb:MA17-2: PIN HEADER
